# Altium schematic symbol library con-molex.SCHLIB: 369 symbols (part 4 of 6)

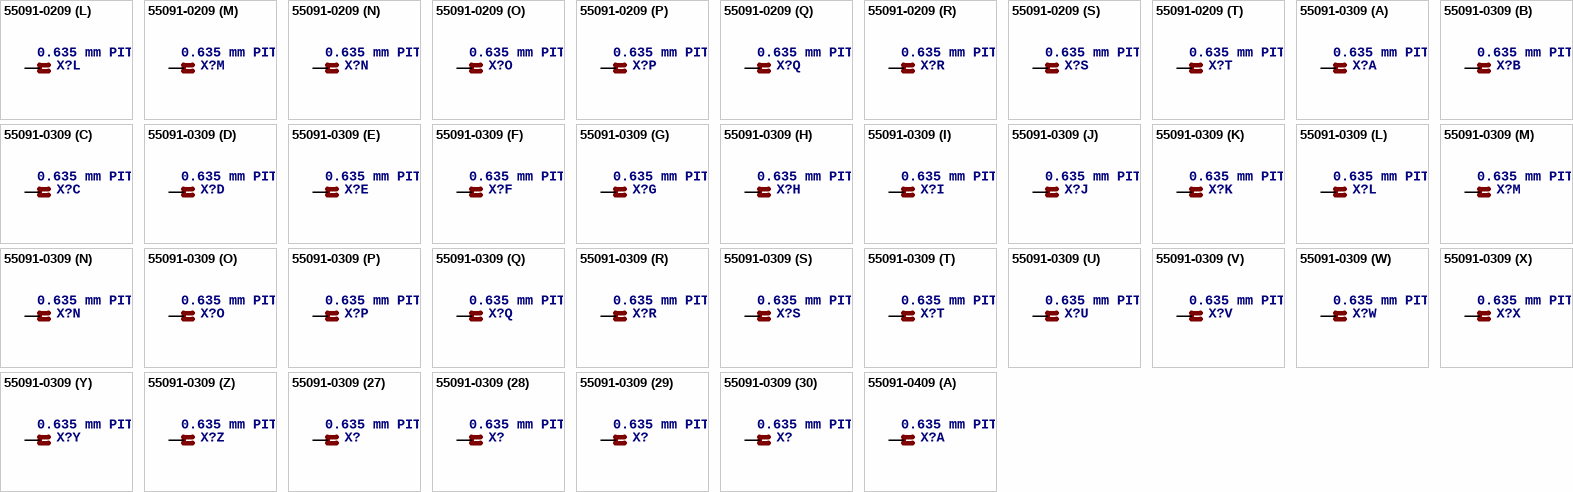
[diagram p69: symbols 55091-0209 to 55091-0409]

## 55091-0209
designator X?, comment 0.635 mm PITCH B TO B CONN.   Source: http://www.molex.com/pdm_docs/sd/550911609_sd.pdf
footprint 55091-0209
part A pins: 1 S
part B pins: 2 S
part C pins: 3 S
part D pins: 4 S
part E pins: 5 S
part F pins: 6 S
part G pins: 7 S
part H pins: 8 S
part I pins: 9 S
part J pins: 10 S
part K pins: 11 S
part L pins: 12 S
part M pins: 13 S
part N pins: 14 S
part O pins: 15 S
part P pins: 16 S
part Q pins: 17 S
part R pins: 18 S
part S pins: 19 S
part T pins: 20 S

## 55091-0309
designator X?, comment 0.635 mm PITCH B TO B CONN.   Source: http://www.molex.com/pdm_docs/sd/550911609_sd.pdf
footprint 55091-0309
part A pins: 1 S
part B pins: 2 S
part C pins: 3 S
part D pins: 4 S
part E pins: 5 S
part F pins: 6 S
part G pins: 7 S
part H pins: 8 S
part I pins: 9 S
part J pins: 10 S
part K pins: 11 S
part L pins: 12 S
part M pins: 13 S
part N pins: 14 S
part O pins: 15 S
part P pins: 16 S
part Q pins: 17 S
part R pins: 18 S
part S pins: 19 S
part T pins: 20 S
part U pins: 21 S
part V pins: 22 S
part W pins: 23 S
part X pins: 24 S
part Y pins: 25 S
part Z pins: 26 S
part 27 pins: 27 S
part 28 pins: 28 S
part 29 pins: 29 S
part 30 pins: 30 S

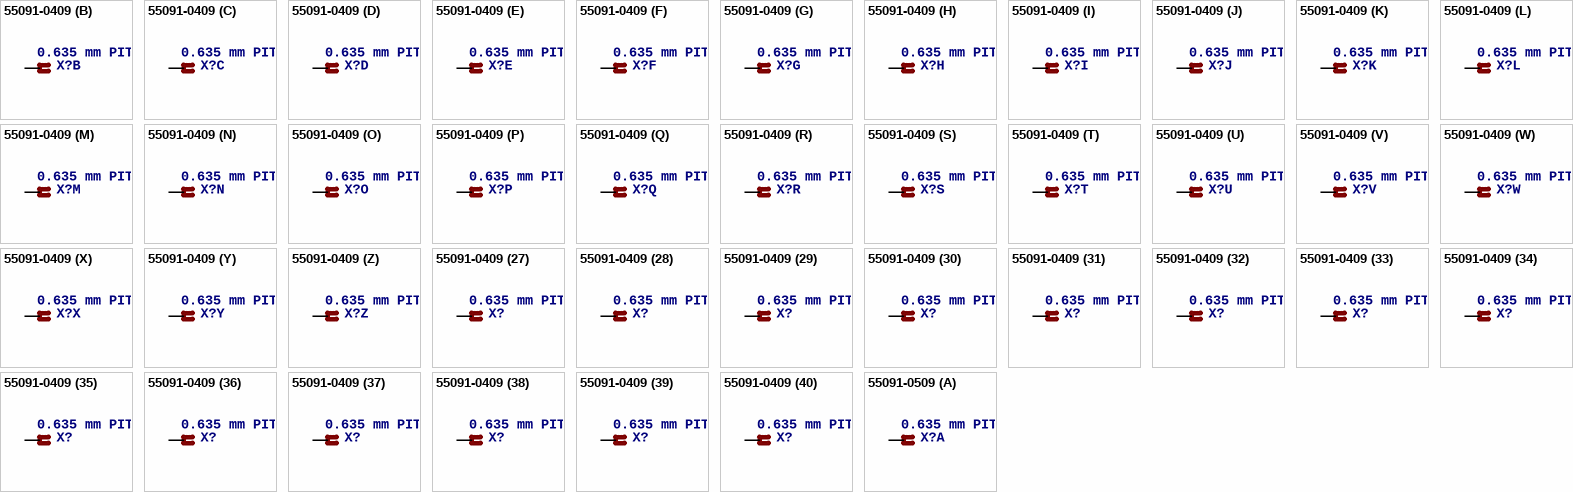
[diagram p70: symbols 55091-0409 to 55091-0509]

## 55091-0409
designator X?, comment 0.635 mm PITCH B TO B CONN.   Source: http://www.molex.com/pdm_docs/sd/550911609_sd.pdf
footprint 55091-0409
part A pins: 1 S
part B pins: 2 S
part C pins: 3 S
part D pins: 4 S
part E pins: 5 S
part F pins: 6 S
part G pins: 7 S
part H pins: 8 S
part I pins: 9 S
part J pins: 10 S
part K pins: 11 S
part L pins: 12 S
part M pins: 13 S
part N pins: 14 S
part O pins: 15 S
part P pins: 16 S
part Q pins: 17 S
part R pins: 18 S
part S pins: 19 S
part T pins: 20 S
part U pins: 21 S
part V pins: 22 S
part W pins: 23 S
part X pins: 24 S
part Y pins: 25 S
part Z pins: 26 S
part 27 pins: 27 S
part 28 pins: 28 S
part 29 pins: 29 S
part 30 pins: 30 S
part 31 pins: 31 S
part 32 pins: 32 S
part 33 pins: 33 S
part 34 pins: 34 S
part 35 pins: 35 S
part 36 pins: 36 S
part 37 pins: 37 S
part 38 pins: 38 S
part 39 pins: 39 S
part 40 pins: 40 S

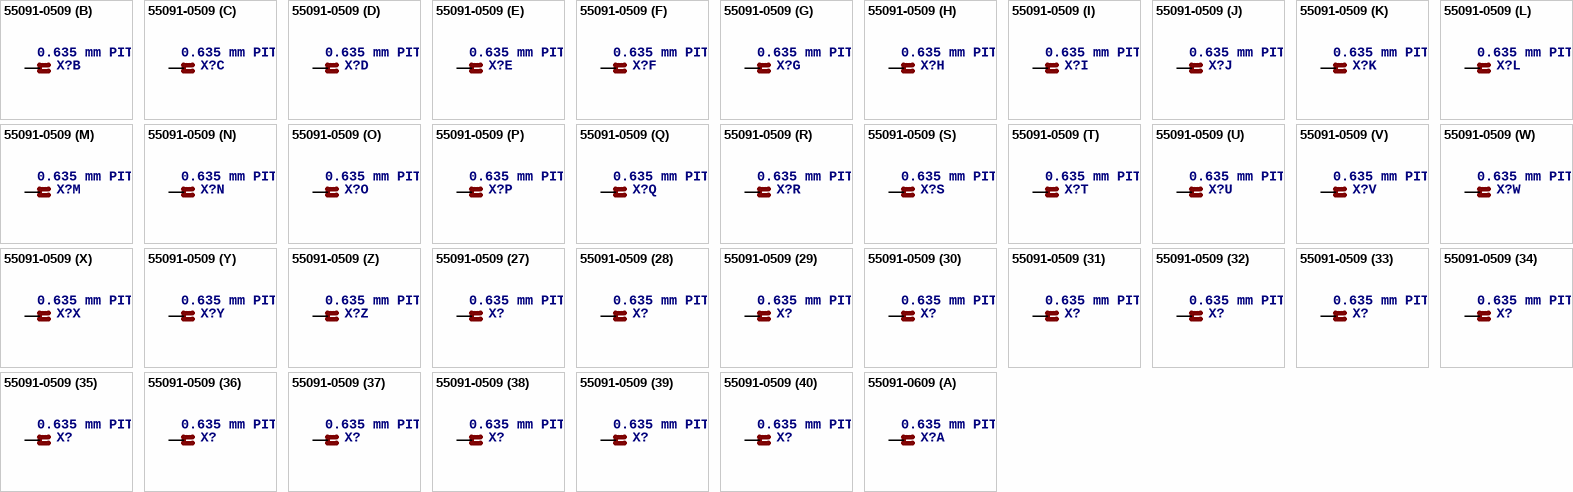
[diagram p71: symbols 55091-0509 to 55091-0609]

## 55091-0509
designator X?, comment 0.635 mm PITCH B TO B CONN.   Source: http://www.molex.com/pdm_docs/sd/550911609_sd.pdf
footprint 55091-0509
part A pins: 1 S
part B pins: 2 S
part C pins: 3 S
part D pins: 4 S
part E pins: 5 S
part F pins: 6 S
part G pins: 7 S
part H pins: 8 S
part I pins: 9 S
part J pins: 10 S
part K pins: 11 S
part L pins: 12 S
part M pins: 13 S
part N pins: 14 S
part O pins: 15 S
part P pins: 16 S
part Q pins: 17 S
part R pins: 18 S
part S pins: 19 S
part T pins: 20 S
part U pins: 21 S
part V pins: 22 S
part W pins: 23 S
part X pins: 24 S
part Y pins: 25 S
part Z pins: 26 S
part 27 pins: 27 S
part 28 pins: 28 S
part 29 pins: 29 S
part 30 pins: 30 S
part 31 pins: 31 S
part 32 pins: 32 S
part 33 pins: 33 S
part 34 pins: 34 S
part 35 pins: 35 S
part 36 pins: 36 S
part 37 pins: 37 S
part 38 pins: 38 S
part 39 pins: 39 S
part 40 pins: 40 S
part 41 pins: 41 S
part 42 pins: 42 S
part 43 pins: 43 S
part 44 pins: 44 S
part 45 pins: 45 S
part 46 pins: 46 S
part 47 pins: 47 S
part 48 pins: 48 S
part 49 pins: 49 S
part 50 pins: 50 S

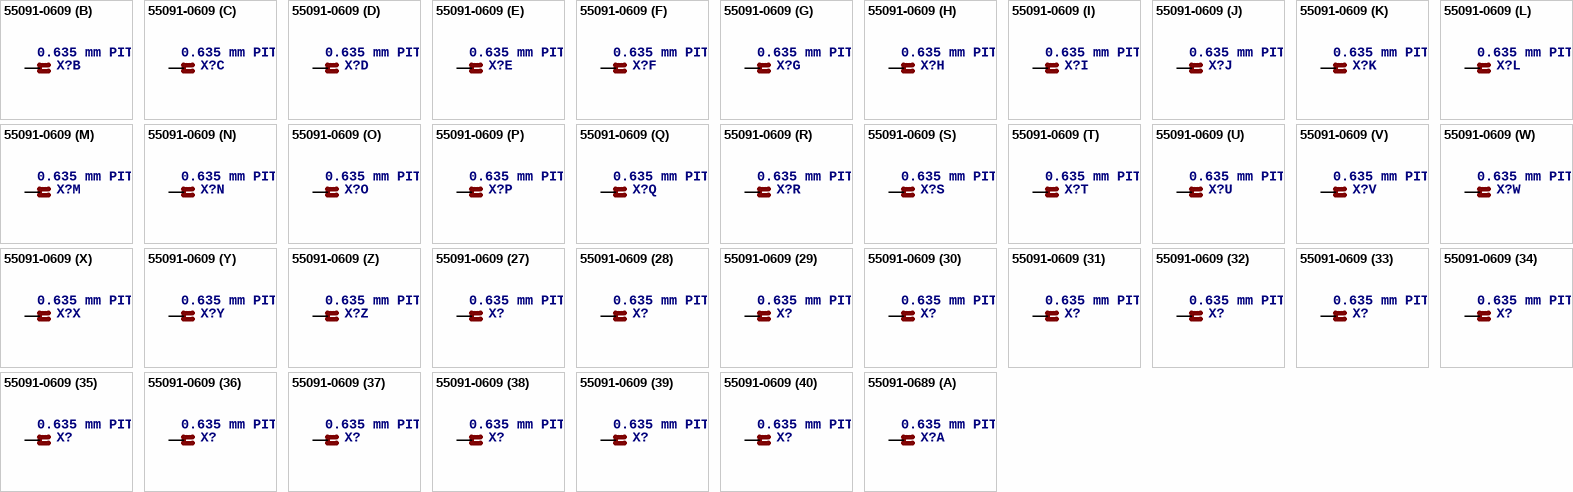
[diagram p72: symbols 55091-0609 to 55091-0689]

## 55091-0609
designator X?, comment 0.635 mm PITCH B TO B CONN.   Source: http://www.molex.com/pdm_docs/sd/550911609_sd.pdf
footprint 55091-0609
part A pins: 1 S
part B pins: 2 S
part C pins: 3 S
part D pins: 4 S
part E pins: 5 S
part F pins: 6 S
part G pins: 7 S
part H pins: 8 S
part I pins: 9 S
part J pins: 10 S
part K pins: 11 S
part L pins: 12 S
part M pins: 13 S
part N pins: 14 S
part O pins: 15 S
part P pins: 16 S
part Q pins: 17 S
part R pins: 18 S
part S pins: 19 S
part T pins: 20 S
part U pins: 21 S
part V pins: 22 S
part W pins: 23 S
part X pins: 24 S
part Y pins: 25 S
part Z pins: 26 S
part 27 pins: 27 S
part 28 pins: 28 S
part 29 pins: 29 S
part 30 pins: 30 S
part 31 pins: 31 S
part 32 pins: 32 S
part 33 pins: 33 S
part 34 pins: 34 S
part 35 pins: 35 S
part 36 pins: 36 S
part 37 pins: 37 S
part 38 pins: 38 S
part 39 pins: 39 S
part 40 pins: 40 S
part 41 pins: 41 S
part 42 pins: 42 S
part 43 pins: 43 S
part 44 pins: 44 S
part 45 pins: 45 S
part 46 pins: 46 S
part 47 pins: 47 S
part 48 pins: 48 S
part 49 pins: 49 S
part 50 pins: 50 S
part 51 pins: 51 S
part 52 pins: 52 S
part 53 pins: 53 S
part 54 pins: 54 S
part 55 pins: 55 S
part 56 pins: 56 S
part 57 pins: 57 S
part 58 pins: 58 S
part 59 pins: 59 S
part 60 pins: 60 S

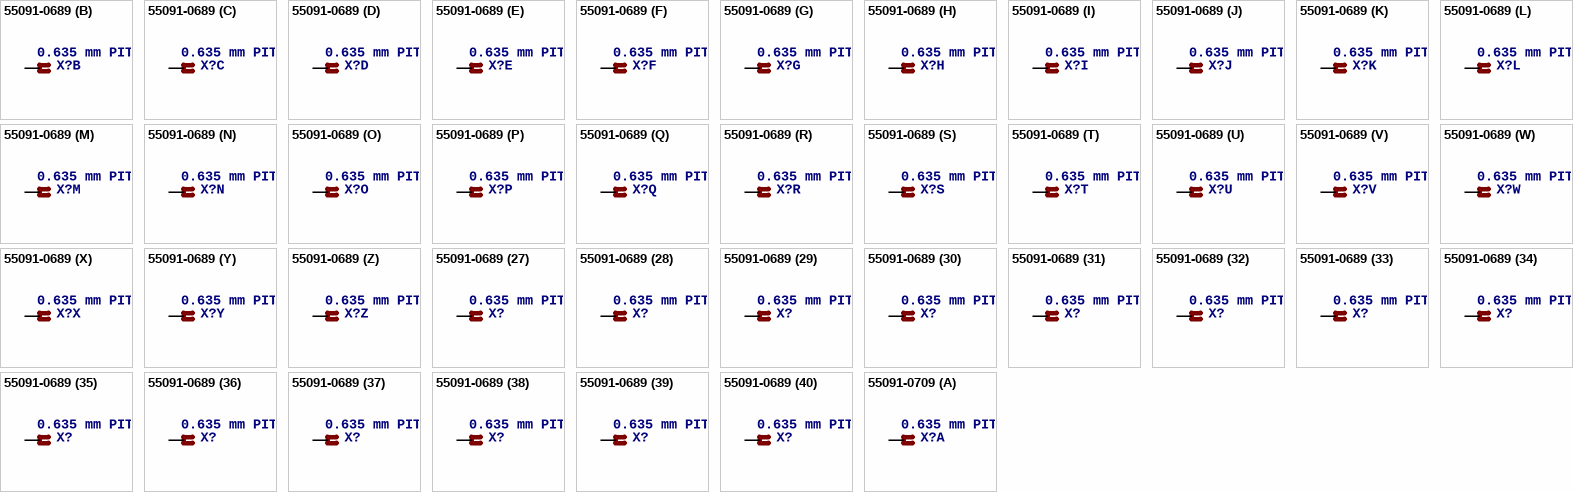
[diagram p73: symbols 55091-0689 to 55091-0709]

## 55091-0689
designator X?, comment 0.635 mm PITCH B TO B CONN.   Source: http://www.molex.com/pdm_docs/sd/550911609_sd.pdf
footprint 55091-0689
part A pins: 1 S
part B pins: 2 S
part C pins: 3 S
part D pins: 4 S
part E pins: 5 S
part F pins: 6 S
part G pins: 7 S
part H pins: 8 S
part I pins: 9 S
part J pins: 10 S
part K pins: 11 S
part L pins: 12 S
part M pins: 13 S
part N pins: 14 S
part O pins: 15 S
part P pins: 16 S
part Q pins: 17 S
part R pins: 18 S
part S pins: 19 S
part T pins: 20 S
part U pins: 21 S
part V pins: 22 S
part W pins: 23 S
part X pins: 24 S
part Y pins: 25 S
part Z pins: 26 S
part 27 pins: 27 S
part 28 pins: 28 S
part 29 pins: 29 S
part 30 pins: 30 S
part 31 pins: 31 S
part 32 pins: 32 S
part 33 pins: 33 S
part 34 pins: 34 S
part 35 pins: 35 S
part 36 pins: 36 S
part 37 pins: 37 S
part 38 pins: 38 S
part 39 pins: 39 S
part 40 pins: 40 S
part 41 pins: 41 S
part 42 pins: 42 S
part 43 pins: 43 S
part 44 pins: 44 S
part 45 pins: 45 S
part 46 pins: 46 S
part 47 pins: 47 S
part 48 pins: 48 S
part 49 pins: 49 S
part 50 pins: 50 S
part 51 pins: 51 S
part 52 pins: 52 S
part 53 pins: 53 S
part 54 pins: 54 S
part 55 pins: 55 S
part 56 pins: 56 S
part 57 pins: 57 S
part 58 pins: 58 S
part 59 pins: 59 S
part 60 pins: 60 S
part 61 pins: 61 S
part 62 pins: 62 S
part 63 pins: 63 S
part 64 pins: 64 S
part 65 pins: 65 S
part 66 pins: 66 S
part 67 pins: 67 S
part 68 pins: 68 S

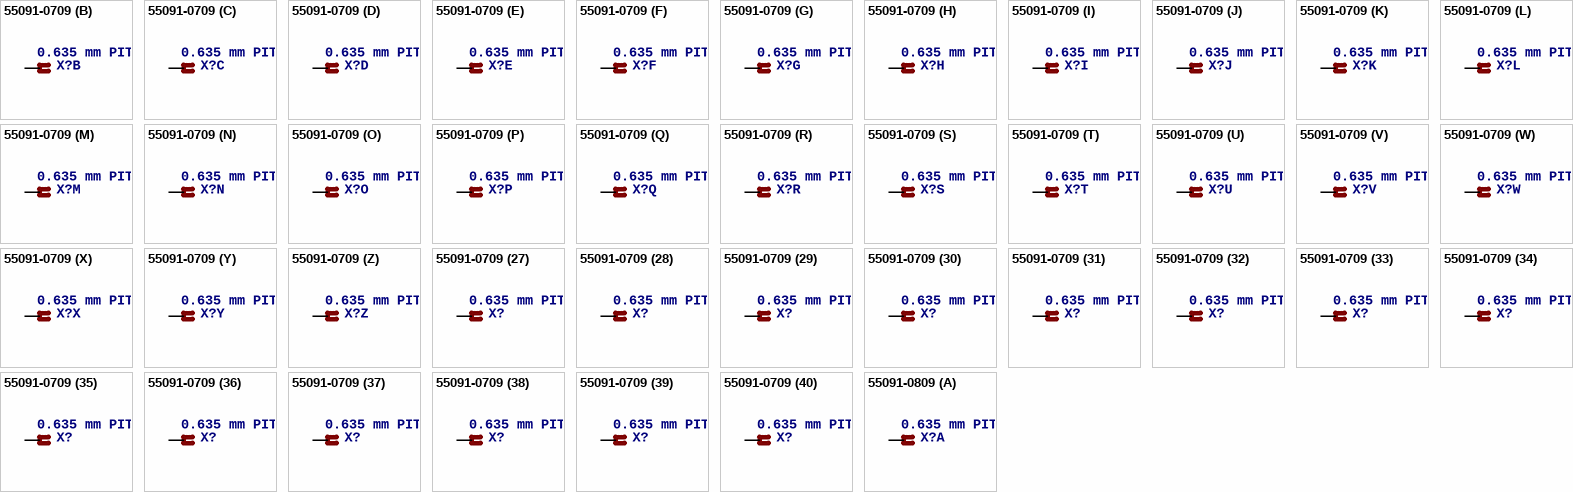
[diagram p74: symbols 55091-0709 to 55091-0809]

## 55091-0709
designator X?, comment 0.635 mm PITCH B TO B CONN.   Source: http://www.molex.com/pdm_docs/sd/550911609_sd.pdf
footprint 55091-0709
part A pins: 1 S
part B pins: 2 S
part C pins: 3 S
part D pins: 4 S
part E pins: 5 S
part F pins: 6 S
part G pins: 7 S
part H pins: 8 S
part I pins: 9 S
part J pins: 10 S
part K pins: 11 S
part L pins: 12 S
part M pins: 13 S
part N pins: 14 S
part O pins: 15 S
part P pins: 16 S
part Q pins: 17 S
part R pins: 18 S
part S pins: 19 S
part T pins: 20 S
part U pins: 21 S
part V pins: 22 S
part W pins: 23 S
part X pins: 24 S
part Y pins: 25 S
part Z pins: 26 S
part 27 pins: 27 S
part 28 pins: 28 S
part 29 pins: 29 S
part 30 pins: 30 S
part 31 pins: 31 S
part 32 pins: 32 S
part 33 pins: 33 S
part 34 pins: 34 S
part 35 pins: 35 S
part 36 pins: 36 S
part 37 pins: 37 S
part 38 pins: 38 S
part 39 pins: 39 S
part 40 pins: 40 S
part 41 pins: 41 S
part 42 pins: 42 S
part 43 pins: 43 S
part 44 pins: 44 S
part 45 pins: 45 S
part 46 pins: 46 S
part 47 pins: 47 S
part 48 pins: 48 S
part 49 pins: 49 S
part 50 pins: 50 S
part 51 pins: 51 S
part 52 pins: 52 S
part 53 pins: 53 S
part 54 pins: 54 S
part 55 pins: 55 S
part 56 pins: 56 S
part 57 pins: 57 S
part 58 pins: 58 S
part 59 pins: 59 S
part 60 pins: 60 S
part 61 pins: 61 S
part 62 pins: 62 S
part 63 pins: 63 S
part 64 pins: 64 S
part 65 pins: 65 S
part 66 pins: 66 S
part 67 pins: 67 S
part 68 pins: 68 S
part 69 pins: 69 S
part 70 pins: 70 S

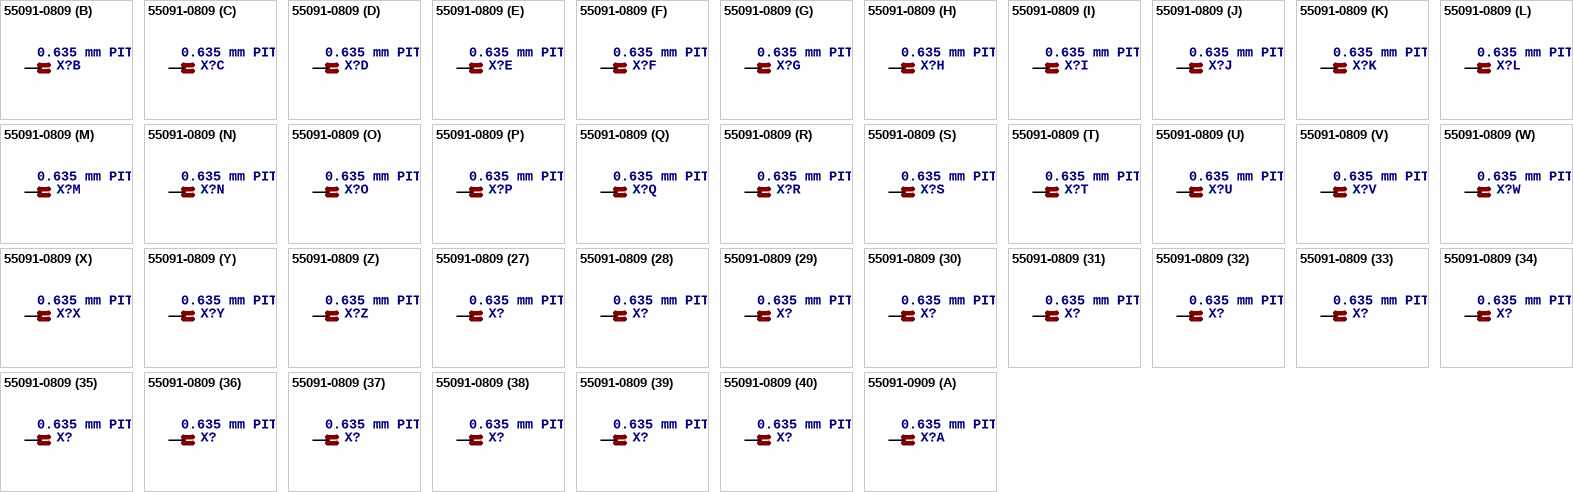
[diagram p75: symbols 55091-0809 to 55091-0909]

## 55091-0809
designator X?, comment 0.635 mm PITCH B TO B CONN.   Source: http://www.molex.com/pdm_docs/sd/550911609_sd.pdf
footprint 55091-0809
part A pins: 1 S
part B pins: 2 S
part C pins: 3 S
part D pins: 4 S
part E pins: 5 S
part F pins: 6 S
part G pins: 7 S
part H pins: 8 S
part I pins: 9 S
part J pins: 10 S
part K pins: 11 S
part L pins: 12 S
part M pins: 13 S
part N pins: 14 S
part O pins: 15 S
part P pins: 16 S
part Q pins: 17 S
part R pins: 18 S
part S pins: 19 S
part T pins: 20 S
part U pins: 21 S
part V pins: 22 S
part W pins: 23 S
part X pins: 24 S
part Y pins: 25 S
part Z pins: 26 S
part 27 pins: 27 S
part 28 pins: 28 S
part 29 pins: 29 S
part 30 pins: 30 S
part 31 pins: 31 S
part 32 pins: 32 S
part 33 pins: 33 S
part 34 pins: 34 S
part 35 pins: 35 S
part 36 pins: 36 S
part 37 pins: 37 S
part 38 pins: 38 S
part 39 pins: 39 S
part 40 pins: 40 S
part 41 pins: 41 S
part 42 pins: 42 S
part 43 pins: 43 S
part 44 pins: 44 S
part 45 pins: 45 S
part 46 pins: 46 S
part 47 pins: 47 S
part 48 pins: 48 S
part 49 pins: 49 S
part 50 pins: 50 S
part 51 pins: 51 S
part 52 pins: 52 S
part 53 pins: 53 S
part 54 pins: 54 S
part 55 pins: 55 S
part 56 pins: 56 S
part 57 pins: 57 S
part 58 pins: 58 S
part 59 pins: 59 S
part 60 pins: 60 S
part 61 pins: 61 S
part 62 pins: 62 S
part 63 pins: 63 S
part 64 pins: 64 S
part 65 pins: 65 S
part 66 pins: 66 S
part 67 pins: 67 S
part 68 pins: 68 S
part 69 pins: 69 S
part 70 pins: 70 S
part 71 pins: 71 S
part 72 pins: 72 S
part 73 pins: 73 S
part 74 pins: 74 S
part 75 pins: 75 S
part 76 pins: 76 S
part 77 pins: 77 S
part 78 pins: 78 S
part 79 pins: 79 S
part 80 pins: 80 S

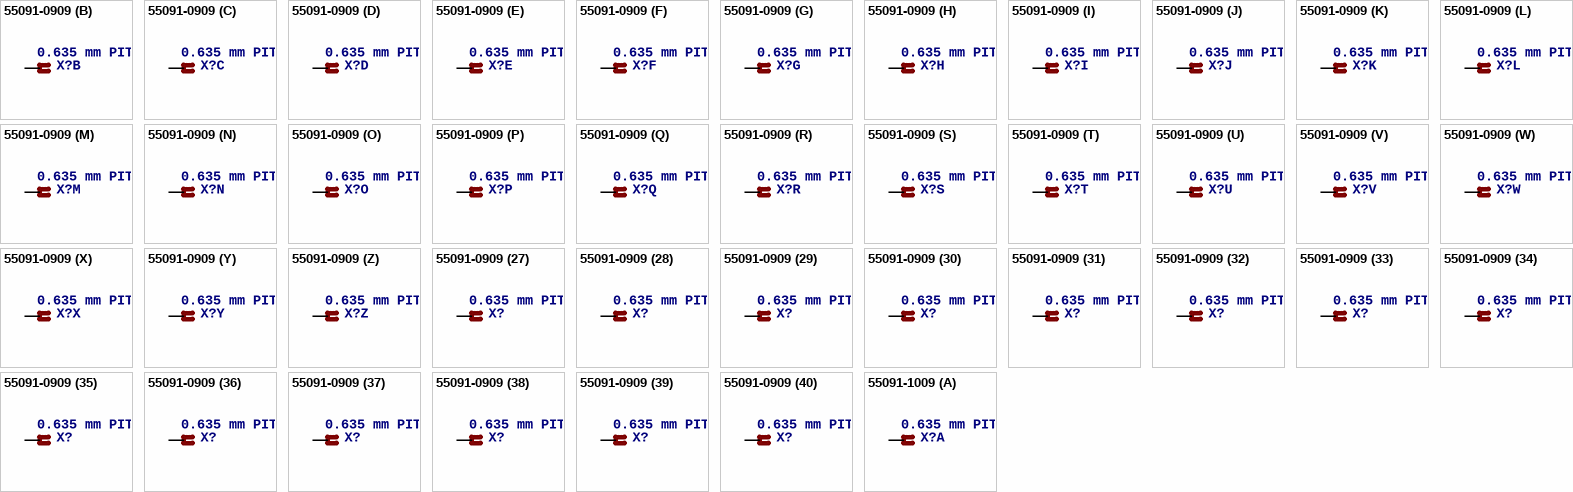
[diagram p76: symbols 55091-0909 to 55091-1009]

## 55091-0909
designator X?, comment 0.635 mm PITCH B TO B CONN.   Source: http://www.molex.com/pdm_docs/sd/550911609_sd.pdf
footprint 55091-0909
part A pins: 1 S
part B pins: 2 S
part C pins: 3 S
part D pins: 4 S
part E pins: 5 S
part F pins: 6 S
part G pins: 7 S
part H pins: 8 S
part I pins: 9 S
part J pins: 10 S
part K pins: 11 S
part L pins: 12 S
part M pins: 13 S
part N pins: 14 S
part O pins: 15 S
part P pins: 16 S
part Q pins: 17 S
part R pins: 18 S
part S pins: 19 S
part T pins: 20 S
part U pins: 21 S
part V pins: 22 S
part W pins: 23 S
part X pins: 24 S
part Y pins: 25 S
part Z pins: 26 S
part 27 pins: 27 S
part 28 pins: 28 S
part 29 pins: 29 S
part 30 pins: 30 S
part 31 pins: 31 S
part 32 pins: 32 S
part 33 pins: 33 S
part 34 pins: 34 S
part 35 pins: 35 S
part 36 pins: 36 S
part 37 pins: 37 S
part 38 pins: 38 S
part 39 pins: 39 S
part 40 pins: 40 S
part 41 pins: 41 S
part 42 pins: 42 S
part 43 pins: 43 S
part 44 pins: 44 S
part 45 pins: 45 S
part 46 pins: 46 S
part 47 pins: 47 S
part 48 pins: 48 S
part 49 pins: 49 S
part 50 pins: 50 S
part 51 pins: 51 S
part 52 pins: 52 S
part 53 pins: 53 S
part 54 pins: 54 S
part 55 pins: 55 S
part 56 pins: 56 S
part 57 pins: 57 S
part 58 pins: 58 S
part 59 pins: 59 S
part 60 pins: 60 S
part 61 pins: 61 S
part 62 pins: 62 S
part 63 pins: 63 S
part 64 pins: 64 S
part 65 pins: 65 S
part 66 pins: 66 S
part 67 pins: 67 S
part 68 pins: 68 S
part 69 pins: 69 S
part 70 pins: 70 S
part 71 pins: 71 S
part 72 pins: 72 S
part 73 pins: 73 S
part 74 pins: 74 S
part 75 pins: 75 S
part 76 pins: 76 S
part 77 pins: 77 S
part 78 pins: 78 S
part 79 pins: 79 S
part 80 pins: 80 S
part 81 pins: 81 S
part 82 pins: 82 S
part 83 pins: 83 S
part 84 pins: 84 S
part 85 pins: 85 S
part 86 pins: 86 S
part 87 pins: 87 S
part 88 pins: 88 S
part 89 pins: 89 S
part 90 pins: 90 S

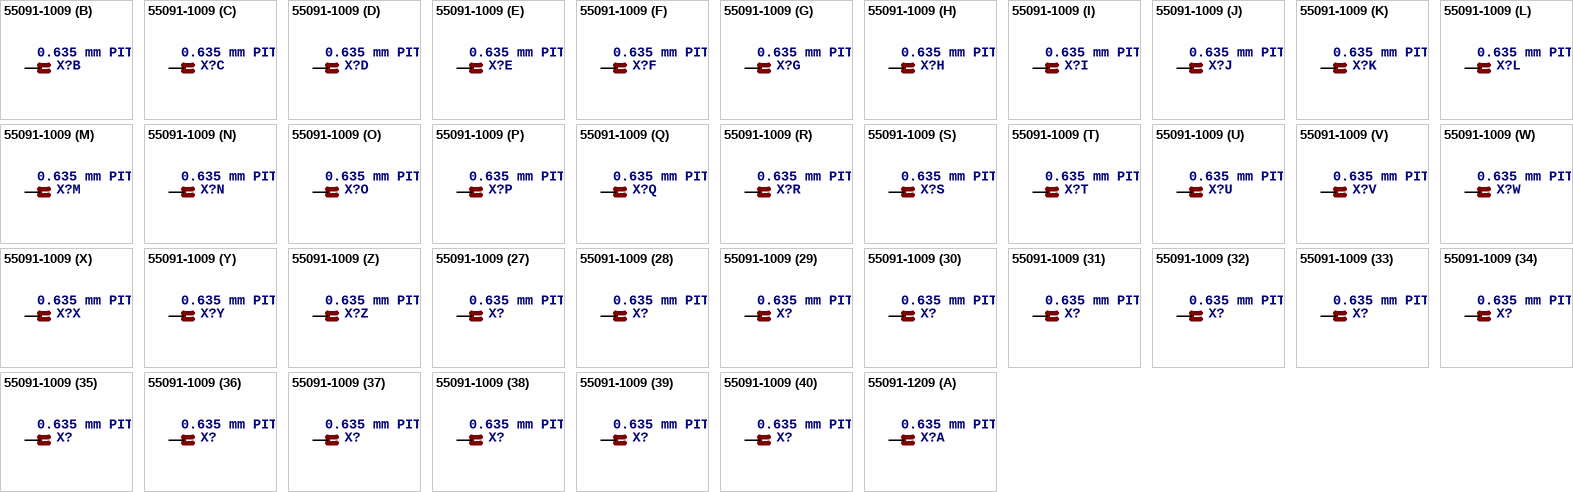
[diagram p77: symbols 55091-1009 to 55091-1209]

## 55091-1009
designator X?, comment 0.635 mm PITCH B TO B CONN.   Source: http://www.molex.com/pdm_docs/sd/550911609_sd.pdf
footprint 55091-1009
part A pins: 1 S
part B pins: 2 S
part C pins: 3 S
part D pins: 4 S
part E pins: 5 S
part F pins: 6 S
part G pins: 7 S
part H pins: 8 S
part I pins: 9 S
part J pins: 10 S
part K pins: 11 S
part L pins: 12 S
part M pins: 13 S
part N pins: 14 S
part O pins: 15 S
part P pins: 16 S
part Q pins: 17 S
part R pins: 18 S
part S pins: 19 S
part T pins: 20 S
part U pins: 21 S
part V pins: 22 S
part W pins: 23 S
part X pins: 24 S
part Y pins: 25 S
part Z pins: 26 S
part 27 pins: 27 S
part 28 pins: 28 S
part 29 pins: 29 S
part 30 pins: 30 S
part 31 pins: 31 S
part 32 pins: 32 S
part 33 pins: 33 S
part 34 pins: 34 S
part 35 pins: 35 S
part 36 pins: 36 S
part 37 pins: 37 S
part 38 pins: 38 S
part 39 pins: 39 S
part 40 pins: 40 S
part 41 pins: 41 S
part 42 pins: 42 S
part 43 pins: 43 S
part 44 pins: 44 S
part 45 pins: 45 S
part 46 pins: 46 S
part 47 pins: 47 S
part 48 pins: 48 S
part 49 pins: 49 S
part 50 pins: 50 S
part 51 pins: 51 S
part 52 pins: 52 S
part 53 pins: 53 S
part 54 pins: 54 S
part 55 pins: 55 S
part 56 pins: 56 S
part 57 pins: 57 S
part 58 pins: 58 S
part 59 pins: 59 S
part 60 pins: 60 S
part 61 pins: 61 S
part 62 pins: 62 S
part 63 pins: 63 S
part 64 pins: 64 S
part 65 pins: 65 S
part 66 pins: 66 S
part 67 pins: 67 S
part 68 pins: 68 S
part 69 pins: 69 S
part 70 pins: 70 S
part 71 pins: 71 S
part 72 pins: 72 S
part 73 pins: 73 S
part 74 pins: 74 S
part 75 pins: 75 S
part 76 pins: 76 S
part 77 pins: 77 S
part 78 pins: 78 S
part 79 pins: 79 S
part 80 pins: 80 S
part 81 pins: 81 S
part 82 pins: 82 S
part 83 pins: 83 S
part 84 pins: 84 S
part 85 pins: 85 S
part 86 pins: 86 S
part 87 pins: 87 S
part 88 pins: 88 S
part 89 pins: 89 S
part 90 pins: 90 S
part 91 pins: 91 S
part 92 pins: 92 S
part 93 pins: 93 S
part 94 pins: 94 S
part 95 pins: 95 S
part 96 pins: 96 S
part 97 pins: 97 S
part 98 pins: 98 S
part 99 pins: 99 S
part 100 pins: 100 S

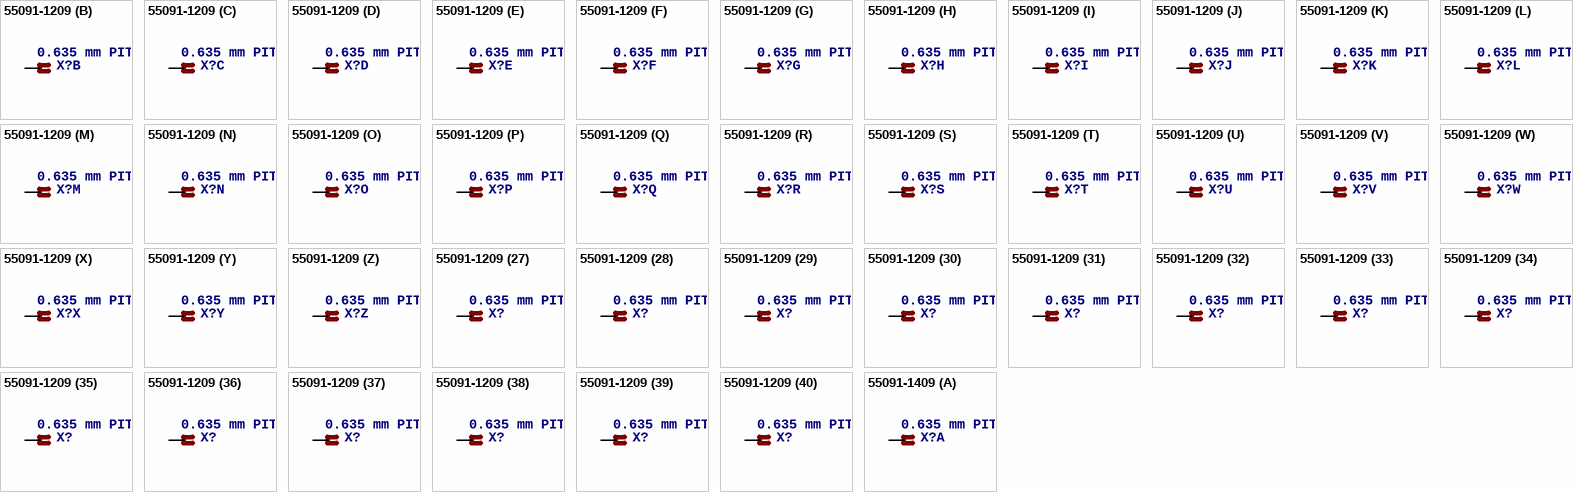
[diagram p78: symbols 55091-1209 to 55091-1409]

## 55091-1209
designator X?, comment 0.635 mm PITCH B TO B CONN.   Source: http://www.molex.com/pdm_docs/sd/550911609_sd.pdf
footprint 55091-1209
part A pins: 1 S
part B pins: 2 S
part C pins: 3 S
part D pins: 4 S
part E pins: 5 S
part F pins: 6 S
part G pins: 7 S
part H pins: 8 S
part I pins: 9 S
part J pins: 10 S
part K pins: 11 S
part L pins: 12 S
part M pins: 13 S
part N pins: 14 S
part O pins: 15 S
part P pins: 16 S
part Q pins: 17 S
part R pins: 18 S
part S pins: 19 S
part T pins: 20 S
part U pins: 21 S
part V pins: 22 S
part W pins: 23 S
part X pins: 24 S
part Y pins: 25 S
part Z pins: 26 S
part 27 pins: 27 S
part 28 pins: 28 S
part 29 pins: 29 S
part 30 pins: 30 S
part 31 pins: 31 S
part 32 pins: 32 S
part 33 pins: 33 S
part 34 pins: 34 S
part 35 pins: 35 S
part 36 pins: 36 S
part 37 pins: 37 S
part 38 pins: 38 S
part 39 pins: 39 S
part 40 pins: 40 S
part 41 pins: 41 S
part 42 pins: 42 S
part 43 pins: 43 S
part 44 pins: 44 S
part 45 pins: 45 S
part 46 pins: 46 S
part 47 pins: 47 S
part 48 pins: 48 S
part 49 pins: 49 S
part 50 pins: 50 S
part 51 pins: 51 S
part 52 pins: 52 S
part 53 pins: 53 S
part 54 pins: 54 S
part 55 pins: 55 S
part 56 pins: 56 S
part 57 pins: 57 S
part 58 pins: 58 S
part 59 pins: 59 S
part 60 pins: 60 S
part 61 pins: 61 S
part 62 pins: 62 S
part 63 pins: 63 S
part 64 pins: 64 S
part 65 pins: 65 S
part 66 pins: 66 S
part 67 pins: 67 S
part 68 pins: 68 S
part 69 pins: 69 S
part 70 pins: 70 S
part 71 pins: 71 S
part 72 pins: 72 S
part 73 pins: 73 S
part 74 pins: 74 S
part 75 pins: 75 S
part 76 pins: 76 S
part 77 pins: 77 S
part 78 pins: 78 S
part 79 pins: 79 S
part 80 pins: 80 S
part 81 pins: 81 S
part 82 pins: 82 S
part 83 pins: 83 S
part 84 pins: 84 S
part 85 pins: 85 S
part 86 pins: 86 S
part 87 pins: 87 S
part 88 pins: 88 S
part 89 pins: 89 S
part 90 pins: 90 S
part 91 pins: 91 S
part 92 pins: 92 S
part 93 pins: 93 S
part 94 pins: 94 S
part 95 pins: 95 S
part 96 pins: 96 S
part 97 pins: 97 S
part 98 pins: 98 S
part 99 pins: 99 S
part 100 pins: 100 S
part 101 pins: 101 S
part 102 pins: 102 S
part 103 pins: 103 S
part 104 pins: 104 S
part 105 pins: 105 S
part 106 pins: 106 S
part 107 pins: 107 S
part 108 pins: 108 S
part 109 pins: 109 S
part 110 pins: 110 S
part 111 pins: 111 S
part 112 pins: 112 S
part 113 pins: 113 S
part 114 pins: 114 S
part 115 pins: 115 S
part 116 pins: 116 S
part 117 pins: 117 S
part 118 pins: 118 S
part 119 pins: 119 S
part 120 pins: 120 S

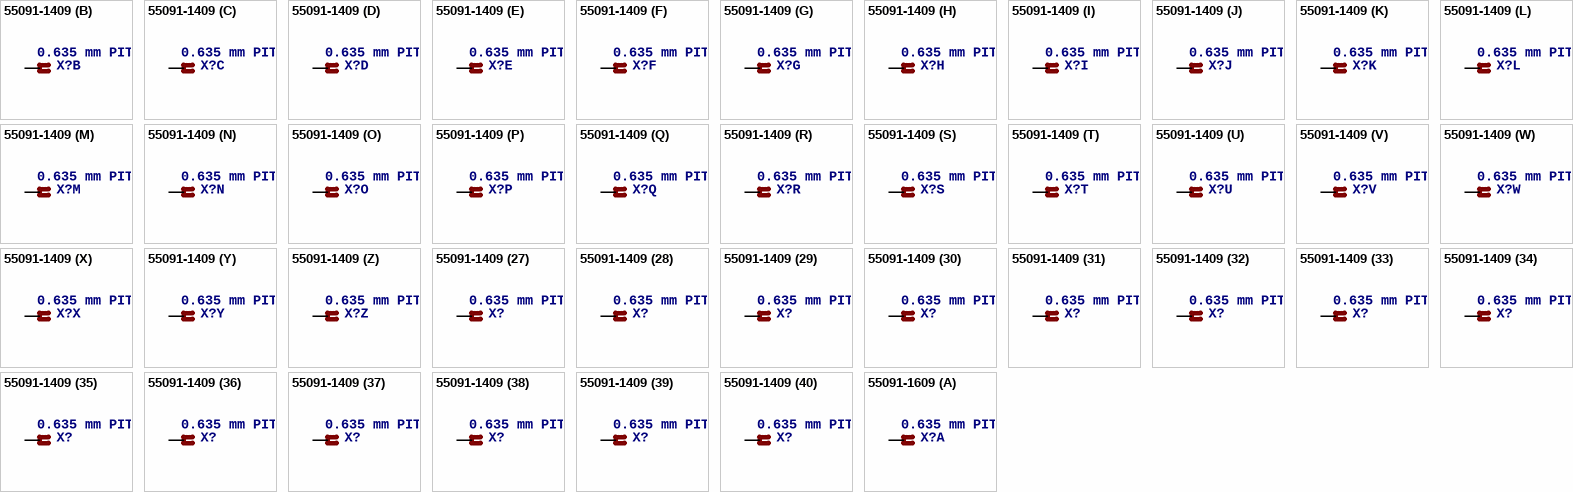
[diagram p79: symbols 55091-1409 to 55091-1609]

## 55091-1409
designator X?, comment 0.635 mm PITCH B TO B CONN.   Source: http://www.molex.com/pdm_docs/sd/550911609_sd.pdf
footprint 55091-1409
part A pins: 1 S
part B pins: 2 S
part C pins: 3 S
part D pins: 4 S
part E pins: 5 S
part F pins: 6 S
part G pins: 7 S
part H pins: 8 S
part I pins: 9 S
part J pins: 10 S
part K pins: 11 S
part L pins: 12 S
part M pins: 13 S
part N pins: 14 S
part O pins: 15 S
part P pins: 16 S
part Q pins: 17 S
part R pins: 18 S
part S pins: 19 S
part T pins: 20 S
part U pins: 21 S
part V pins: 22 S
part W pins: 23 S
part X pins: 24 S
part Y pins: 25 S
part Z pins: 26 S
part 27 pins: 27 S
part 28 pins: 28 S
part 29 pins: 29 S
part 30 pins: 30 S
part 31 pins: 31 S
part 32 pins: 32 S
part 33 pins: 33 S
part 34 pins: 34 S
part 35 pins: 35 S
part 36 pins: 36 S
part 37 pins: 37 S
part 38 pins: 38 S
part 39 pins: 39 S
part 40 pins: 40 S
part 41 pins: 41 S
part 42 pins: 42 S
part 43 pins: 43 S
part 44 pins: 44 S
part 45 pins: 45 S
part 46 pins: 46 S
part 47 pins: 47 S
part 48 pins: 48 S
part 49 pins: 49 S
part 50 pins: 50 S
part 51 pins: 51 S
part 52 pins: 52 S
part 53 pins: 53 S
part 54 pins: 54 S
part 55 pins: 55 S
part 56 pins: 56 S
part 57 pins: 57 S
part 58 pins: 58 S
part 59 pins: 59 S
part 60 pins: 60 S
part 61 pins: 61 S
part 62 pins: 62 S
part 63 pins: 63 S
part 64 pins: 64 S
part 65 pins: 65 S
part 66 pins: 66 S
part 67 pins: 67 S
part 68 pins: 68 S
part 69 pins: 69 S
part 70 pins: 70 S
part 71 pins: 71 S
part 72 pins: 72 S
part 73 pins: 73 S
part 74 pins: 74 S
part 75 pins: 75 S
part 76 pins: 76 S
part 77 pins: 77 S
part 78 pins: 78 S
part 79 pins: 79 S
part 80 pins: 80 S
part 81 pins: 81 S
part 82 pins: 82 S
part 83 pins: 83 S
part 84 pins: 84 S
part 85 pins: 85 S
part 86 pins: 86 S
part 87 pins: 87 S
part 88 pins: 88 S
part 89 pins: 89 S
part 90 pins: 90 S
part 91 pins: 91 S
part 92 pins: 92 S
part 93 pins: 93 S
part 94 pins: 94 S
part 95 pins: 95 S
part 96 pins: 96 S
part 97 pins: 97 S
part 98 pins: 98 S
part 99 pins: 99 S
part 100 pins: 100 S
part 101 pins: 101 S
part 102 pins: 102 S
part 103 pins: 103 S
part 104 pins: 104 S
part 105 pins: 105 S
part 106 pins: 106 S
part 107 pins: 107 S
part 108 pins: 108 S
part 109 pins: 109 S
part 110 pins: 110 S
part 111 pins: 111 S
part 112 pins: 112 S
part 113 pins: 113 S
part 114 pins: 114 S
part 115 pins: 115 S
part 116 pins: 116 S
part 117 pins: 117 S
part 118 pins: 118 S
part 119 pins: 119 S
part 120 pins: 120 S
part 121 pins: 121 S
part 122 pins: 122 S
part 123 pins: 123 S
part 124 pins: 124 S
part 125 pins: 125 S
part 126 pins: 126 S
part 127 pins: 127 S
part 128 pins: 128 S
part 129 pins: 129 S
part 130 pins: 130 S
part 131 pins: 131 S
part 132 pins: 132 S
part 133 pins: 133 S
part 134 pins: 134 S
part 135 pins: 135 S
part 136 pins: 136 S
part 137 pins: 137 S
part 138 pins: 138 S
part 139 pins: 139 S
part 140 pins: 140 S

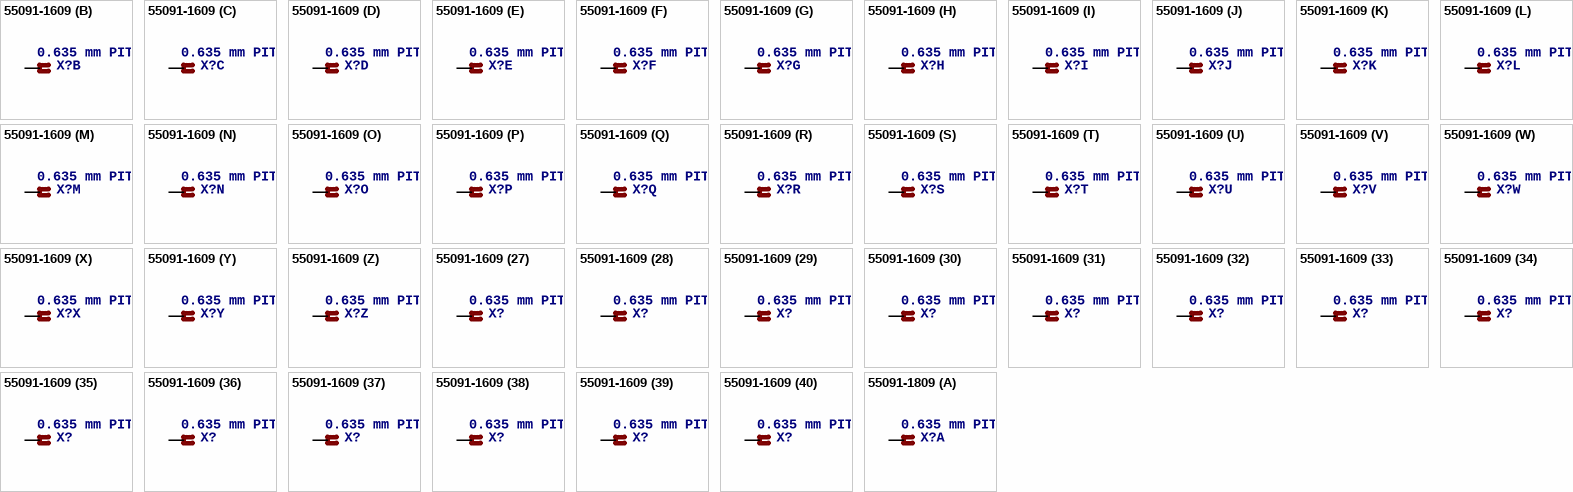
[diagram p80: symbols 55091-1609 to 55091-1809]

## 55091-1609
designator X?, comment 0.635 mm PITCH B TO B CONN.   Source: http://www.molex.com/pdm_docs/sd/550911609_sd.pdf
footprint 55091-1609
part A pins: 1 S
part B pins: 2 S
part C pins: 3 S
part D pins: 4 S
part E pins: 5 S
part F pins: 6 S
part G pins: 7 S
part H pins: 8 S
part I pins: 9 S
part J pins: 10 S
part K pins: 11 S
part L pins: 12 S
part M pins: 13 S
part N pins: 14 S
part O pins: 15 S
part P pins: 16 S
part Q pins: 17 S
part R pins: 18 S
part S pins: 19 S
part T pins: 20 S
part U pins: 21 S
part V pins: 22 S
part W pins: 23 S
part X pins: 24 S
part Y pins: 25 S
part Z pins: 26 S
part 27 pins: 27 S
part 28 pins: 28 S
part 29 pins: 29 S
part 30 pins: 30 S
part 31 pins: 31 S
part 32 pins: 32 S
part 33 pins: 33 S
part 34 pins: 34 S
part 35 pins: 35 S
part 36 pins: 36 S
part 37 pins: 37 S
part 38 pins: 38 S
part 39 pins: 39 S
part 40 pins: 40 S
part 41 pins: 41 S
part 42 pins: 42 S
part 43 pins: 43 S
part 44 pins: 44 S
part 45 pins: 45 S
part 46 pins: 46 S
part 47 pins: 47 S
part 48 pins: 48 S
part 49 pins: 49 S
part 50 pins: 50 S
part 51 pins: 51 S
part 52 pins: 52 S
part 53 pins: 53 S
part 54 pins: 54 S
part 55 pins: 55 S
part 56 pins: 56 S
part 57 pins: 57 S
part 58 pins: 58 S
part 59 pins: 59 S
part 60 pins: 60 S
part 61 pins: 61 S
part 62 pins: 62 S
part 63 pins: 63 S
part 64 pins: 64 S
part 65 pins: 65 S
part 66 pins: 66 S
part 67 pins: 67 S
part 68 pins: 68 S
part 69 pins: 69 S
part 70 pins: 70 S
part 71 pins: 71 S
part 72 pins: 72 S
part 73 pins: 73 S
part 74 pins: 74 S
part 75 pins: 75 S
part 76 pins: 76 S
part 77 pins: 77 S
part 78 pins: 78 S
part 79 pins: 79 S
part 80 pins: 80 S
part 81 pins: 81 S
part 82 pins: 82 S
part 83 pins: 83 S
part 84 pins: 84 S
part 85 pins: 85 S
part 86 pins: 86 S
part 87 pins: 87 S
part 88 pins: 88 S
part 89 pins: 89 S
part 90 pins: 90 S
part 91 pins: 91 S
part 92 pins: 92 S
part 93 pins: 93 S
part 94 pins: 94 S
part 95 pins: 95 S
part 96 pins: 96 S
part 97 pins: 97 S
part 98 pins: 98 S
part 99 pins: 99 S
part 100 pins: 100 S
part 101 pins: 101 S
part 102 pins: 102 S
part 103 pins: 103 S
part 104 pins: 104 S
part 105 pins: 105 S
part 106 pins: 106 S
part 107 pins: 107 S
part 108 pins: 108 S
part 109 pins: 109 S
part 110 pins: 110 S
part 111 pins: 111 S
part 112 pins: 112 S
part 113 pins: 113 S
part 114 pins: 114 S
part 115 pins: 115 S
part 116 pins: 116 S
part 117 pins: 117 S
part 118 pins: 118 S
part 119 pins: 119 S
part 120 pins: 120 S
part 121 pins: 121 S
part 122 pins: 122 S
part 123 pins: 123 S
part 124 pins: 124 S
part 125 pins: 125 S
part 126 pins: 126 S
part 127 pins: 127 S
part 128 pins: 128 S
part 129 pins: 129 S
part 130 pins: 130 S
part 131 pins: 131 S
part 132 pins: 132 S
part 133 pins: 133 S
part 134 pins: 134 S
part 135 pins: 135 S
part 136 pins: 136 S
part 137 pins: 137 S
part 138 pins: 138 S
part 139 pins: 139 S
part 140 pins: 140 S
part 141 pins: 141 S
part 142 pins: 142 S
part 143 pins: 143 S
part 144 pins: 144 S
part 145 pins: 145 S
part 146 pins: 146 S
part 147 pins: 147 S
part 148 pins: 148 S
part 149 pins: 149 S
part 150 pins: 150 S
part 151 pins: 151 S
part 152 pins: 152 S
part 153 pins: 153 S
part 154 pins: 154 S
part 155 pins: 155 S
part 156 pins: 156 S
part 157 pins: 157 S
part 158 pins: 158 S
part 159 pins: 159 S
part 160 pins: 160 S

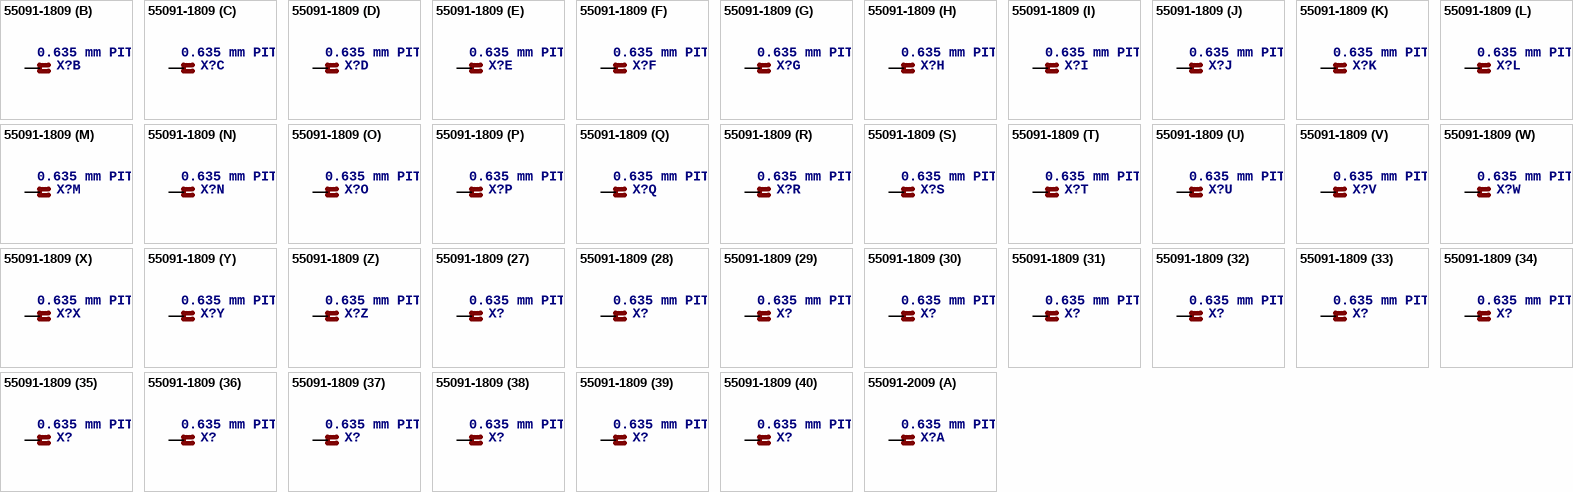
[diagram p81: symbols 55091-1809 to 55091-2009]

## 55091-1809
designator X?, comment 0.635 mm PITCH B TO B CONN.   Source: http://www.molex.com/pdm_docs/sd/550911609_sd.pdf
footprint 55091-1809
part A pins: 1 S
part B pins: 2 S
part C pins: 3 S
part D pins: 4 S
part E pins: 5 S
part F pins: 6 S
part G pins: 7 S
part H pins: 8 S
part I pins: 9 S
part J pins: 10 S
part K pins: 11 S
part L pins: 12 S
part M pins: 13 S
part N pins: 14 S
part O pins: 15 S
part P pins: 16 S
part Q pins: 17 S
part R pins: 18 S
part S pins: 19 S
part T pins: 20 S
part U pins: 21 S
part V pins: 22 S
part W pins: 23 S
part X pins: 24 S
part Y pins: 25 S
part Z pins: 26 S
part 27 pins: 27 S
part 28 pins: 28 S
part 29 pins: 29 S
part 30 pins: 30 S
part 31 pins: 31 S
part 32 pins: 32 S
part 33 pins: 33 S
part 34 pins: 34 S
part 35 pins: 35 S
part 36 pins: 36 S
part 37 pins: 37 S
part 38 pins: 38 S
part 39 pins: 39 S
part 40 pins: 40 S
part 41 pins: 41 S
part 42 pins: 42 S
part 43 pins: 43 S
part 44 pins: 44 S
part 45 pins: 45 S
part 46 pins: 46 S
part 47 pins: 47 S
part 48 pins: 48 S
part 49 pins: 49 S
part 50 pins: 50 S
part 51 pins: 51 S
part 52 pins: 52 S
part 53 pins: 53 S
part 54 pins: 54 S
part 55 pins: 55 S
part 56 pins: 56 S
part 57 pins: 57 S
part 58 pins: 58 S
part 59 pins: 59 S
part 60 pins: 60 S
part 61 pins: 61 S
part 62 pins: 62 S
part 63 pins: 63 S
part 64 pins: 64 S
part 65 pins: 65 S
part 66 pins: 66 S
part 67 pins: 67 S
part 68 pins: 68 S
part 69 pins: 69 S
part 70 pins: 70 S
part 71 pins: 71 S
part 72 pins: 72 S
part 73 pins: 73 S
part 74 pins: 74 S
part 75 pins: 75 S
part 76 pins: 76 S
part 77 pins: 77 S
part 78 pins: 78 S
part 79 pins: 79 S
part 80 pins: 80 S
part 81 pins: 81 S
part 82 pins: 82 S
part 83 pins: 83 S
part 84 pins: 84 S
part 85 pins: 85 S
part 86 pins: 86 S
part 87 pins: 87 S
part 88 pins: 88 S
part 89 pins: 89 S
part 90 pins: 90 S
part 91 pins: 91 S
part 92 pins: 92 S
part 93 pins: 93 S
part 94 pins: 94 S
part 95 pins: 95 S
part 96 pins: 96 S
part 97 pins: 97 S
part 98 pins: 98 S
part 99 pins: 99 S
part 100 pins: 100 S
part 101 pins: 101 S
part 102 pins: 102 S
part 103 pins: 103 S
part 104 pins: 104 S
part 105 pins: 105 S
part 106 pins: 106 S
part 107 pins: 107 S
part 108 pins: 108 S
part 109 pins: 109 S
part 110 pins: 110 S
part 111 pins: 111 S
part 112 pins: 112 S
part 113 pins: 113 S
part 114 pins: 114 S
part 115 pins: 115 S
part 116 pins: 116 S
part 117 pins: 117 S
part 118 pins: 118 S
part 119 pins: 119 S
part 120 pins: 120 S
part 121 pins: 121 S
part 122 pins: 122 S
part 123 pins: 123 S
part 124 pins: 124 S
part 125 pins: 125 S
part 126 pins: 126 S
part 127 pins: 127 S
part 128 pins: 128 S
part 129 pins: 129 S
part 130 pins: 130 S
part 131 pins: 131 S
part 132 pins: 132 S
part 133 pins: 133 S
part 134 pins: 134 S
part 135 pins: 135 S
part 136 pins: 136 S
part 137 pins: 137 S
part 138 pins: 138 S
part 139 pins: 139 S
part 140 pins: 140 S
part 141 pins: 141 S
part 142 pins: 142 S
part 143 pins: 143 S
part 144 pins: 144 S
part 145 pins: 145 S
part 146 pins: 146 S
part 147 pins: 147 S
part 148 pins: 148 S
part 149 pins: 149 S
part 150 pins: 150 S
part 151 pins: 151 S
part 152 pins: 152 S
part 153 pins: 153 S
part 154 pins: 154 S
part 155 pins: 155 S
part 156 pins: 156 S
part 157 pins: 157 S
part 158 pins: 158 S
part 159 pins: 159 S
part 160 pins: 160 S
part 161 pins: 161 S
part 162 pins: 162 S
part 163 pins: 163 S
part 164 pins: 164 S
part 165 pins: 165 S
part 166 pins: 166 S
part 167 pins: 167 S
part 168 pins: 168 S
part 169 pins: 169 S
part 170 pins: 170 S
part 171 pins: 171 S
part 172 pins: 172 S
part 173 pins: 173 S
part 174 pins: 174 S
part 175 pins: 175 S
part 176 pins: 176 S
part 177 pins: 177 S
part 178 pins: 178 S
part 179 pins: 179 S
part 180 pins: 180 S

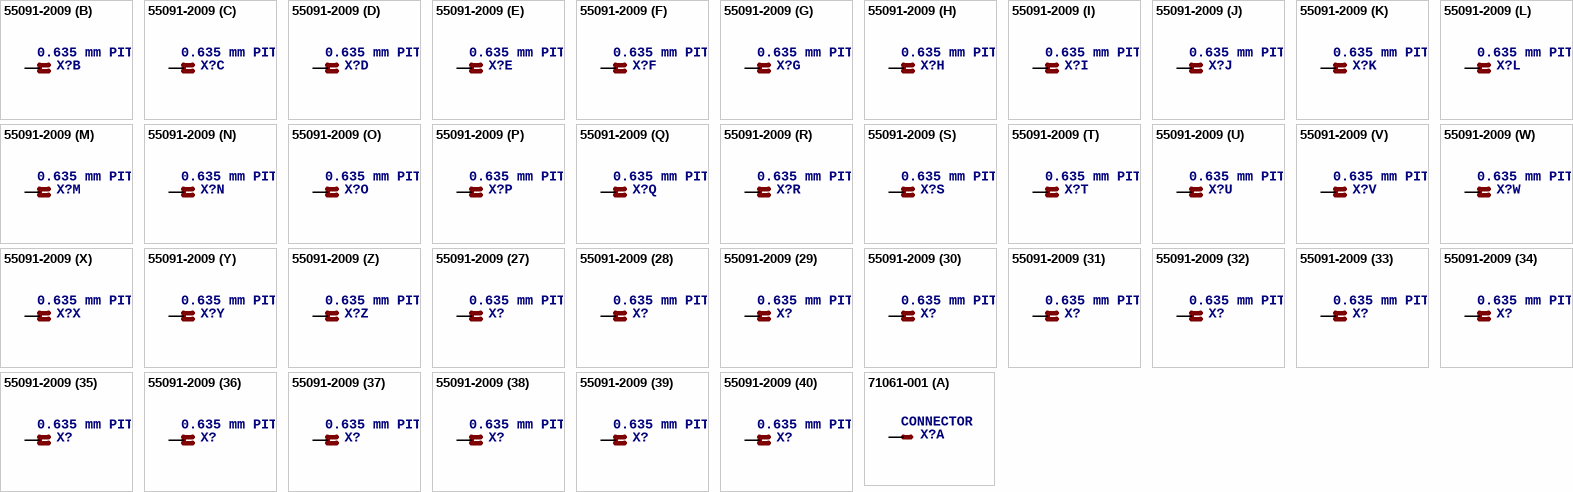
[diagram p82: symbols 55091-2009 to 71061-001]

## 55091-2009
designator X?, comment 0.635 mm PITCH B TO B CONN.   Source: http://www.molex.com/pdm_docs/sd/550911609_sd.pdf
footprint 55091-2009
part A pins: 1 S
part B pins: 2 S
part C pins: 3 S
part D pins: 4 S
part E pins: 5 S
part F pins: 6 S
part G pins: 7 S
part H pins: 8 S
part I pins: 9 S
part J pins: 10 S
part K pins: 11 S
part L pins: 12 S
part M pins: 13 S
part N pins: 14 S
part O pins: 15 S
part P pins: 16 S
part Q pins: 17 S
part R pins: 18 S
part S pins: 19 S
part T pins: 20 S
part U pins: 21 S
part V pins: 22 S
part W pins: 23 S
part X pins: 24 S
part Y pins: 25 S
part Z pins: 26 S
part 27 pins: 27 S
part 28 pins: 28 S
part 29 pins: 29 S
part 30 pins: 30 S
part 31 pins: 31 S
part 32 pins: 32 S
part 33 pins: 33 S
part 34 pins: 34 S
part 35 pins: 35 S
part 36 pins: 36 S
part 37 pins: 37 S
part 38 pins: 38 S
part 39 pins: 39 S
part 40 pins: 40 S
part 41 pins: 41 S
part 42 pins: 42 S
part 43 pins: 43 S
part 44 pins: 44 S
part 45 pins: 45 S
part 46 pins: 46 S
part 47 pins: 47 S
part 48 pins: 48 S
part 49 pins: 49 S
part 50 pins: 50 S
part 51 pins: 51 S
part 52 pins: 52 S
part 53 pins: 53 S
part 54 pins: 54 S
part 55 pins: 55 S
part 56 pins: 56 S
part 57 pins: 57 S
part 58 pins: 58 S
part 59 pins: 59 S
part 60 pins: 60 S
part 61 pins: 61 S
part 62 pins: 62 S
part 63 pins: 63 S
part 64 pins: 64 S
part 65 pins: 65 S
part 66 pins: 66 S
part 67 pins: 67 S
part 68 pins: 68 S
part 69 pins: 69 S
part 70 pins: 70 S
part 71 pins: 71 S
part 72 pins: 72 S
part 73 pins: 73 S
part 74 pins: 74 S
part 75 pins: 75 S
part 76 pins: 76 S
part 77 pins: 77 S
part 78 pins: 78 S
part 79 pins: 79 S
part 80 pins: 80 S
part 81 pins: 81 S
part 82 pins: 82 S
part 83 pins: 83 S
part 84 pins: 84 S
part 85 pins: 85 S
part 86 pins: 86 S
part 87 pins: 87 S
part 88 pins: 88 S
part 89 pins: 89 S
part 90 pins: 90 S
part 91 pins: 91 S
part 92 pins: 92 S
part 93 pins: 93 S
part 94 pins: 94 S
part 95 pins: 95 S
part 96 pins: 96 S
part 97 pins: 97 S
part 98 pins: 98 S
part 99 pins: 99 S
part 100 pins: 100 S
part 101 pins: 101 S
part 102 pins: 102 S
part 103 pins: 103 S
part 104 pins: 104 S
part 105 pins: 105 S
part 106 pins: 106 S
part 107 pins: 107 S
part 108 pins: 108 S
part 109 pins: 109 S
part 110 pins: 110 S
part 111 pins: 111 S
part 112 pins: 112 S
part 113 pins: 113 S
part 114 pins: 114 S
part 115 pins: 115 S
part 116 pins: 116 S
part 117 pins: 117 S
part 118 pins: 118 S
part 119 pins: 119 S
part 120 pins: 120 S
part 121 pins: 121 S
part 122 pins: 122 S
part 123 pins: 123 S
part 124 pins: 124 S
part 125 pins: 125 S
part 126 pins: 126 S
part 127 pins: 127 S
part 128 pins: 128 S
part 129 pins: 129 S
part 130 pins: 130 S
part 131 pins: 131 S
part 132 pins: 132 S
part 133 pins: 133 S
part 134 pins: 134 S
part 135 pins: 135 S
part 136 pins: 136 S
part 137 pins: 137 S
part 138 pins: 138 S
part 139 pins: 139 S
part 140 pins: 140 S
part 141 pins: 141 S
part 142 pins: 142 S
part 143 pins: 143 S
part 144 pins: 144 S
part 145 pins: 145 S
part 146 pins: 146 S
part 147 pins: 147 S
part 148 pins: 148 S
part 149 pins: 149 S
part 150 pins: 150 S
part 151 pins: 151 S
part 152 pins: 152 S
part 153 pins: 153 S
part 154 pins: 154 S
part 155 pins: 155 S
part 156 pins: 156 S
part 157 pins: 157 S
part 158 pins: 158 S
part 159 pins: 159 S
part 160 pins: 160 S
part 161 pins: 161 S
part 162 pins: 162 S
part 163 pins: 163 S
part 164 pins: 164 S
part 165 pins: 165 S
part 166 pins: 166 S
part 167 pins: 167 S
part 168 pins: 168 S
part 169 pins: 169 S
part 170 pins: 170 S
part 171 pins: 171 S
part 172 pins: 172 S
part 173 pins: 173 S
part 174 pins: 174 S
part 175 pins: 175 S
part 176 pins: 176 S
part 177 pins: 177 S
part 178 pins: 178 S
part 179 pins: 179 S
part 180 pins: 180 S
part 181 pins: 181 S
part 182 pins: 182 S
part 183 pins: 183 S
part 184 pins: 184 S
part 185 pins: 185 S
part 186 pins: 186 S
part 187 pins: 187 S
part 188 pins: 188 S
part 189 pins: 189 S
part 190 pins: 190 S
part 191 pins: 191 S
part 192 pins: 192 S
part 193 pins: 193 S
part 194 pins: 194 S
part 195 pins: 195 S
part 196 pins: 196 S
part 197 pins: 197 S
part 198 pins: 198 S
part 199 pins: 199 S
part 200 pins: 200 S

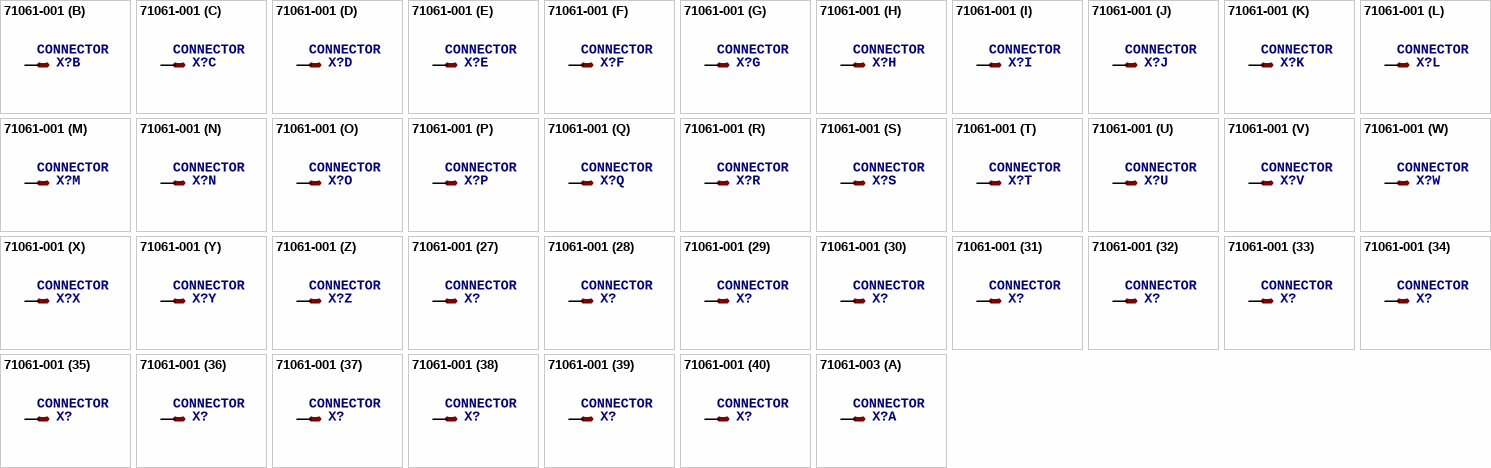
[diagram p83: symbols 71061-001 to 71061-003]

## 71061-001
designator X?, comment CONNECTOR   50-pin 1.27mm (.050 inch) pitch SCSI+ unshielded receptacle   right angle   all plastic
footprint 71061-0001
part A pins: 1 S
part B pins: 2 S
part C pins: 3 S
part D pins: 4 S
part E pins: 5 S
part F pins: 6 S
part G pins: 7 S
part H pins: 8 S
part I pins: 9 S
part J pins: 10 S
part K pins: 11 S
part L pins: 12 S
part M pins: 13 S
part N pins: 14 S
part O pins: 15 S
part P pins: 16 S
part Q pins: 17 S
part R pins: 18 S
part S pins: 19 S
part T pins: 20 S
part U pins: 21 S
part V pins: 22 S
part W pins: 23 S
part X pins: 24 S
part Y pins: 25 S
part Z pins: 26 S
part 27 pins: 27 S
part 28 pins: 28 S
part 29 pins: 29 S
part 30 pins: 30 S
part 31 pins: 31 S
part 32 pins: 32 S
part 33 pins: 33 S
part 34 pins: 34 S
part 35 pins: 35 S
part 36 pins: 36 S
part 37 pins: 37 S
part 38 pins: 38 S
part 39 pins: 39 S
part 40 pins: 40 S
part 41 pins: 41 S
part 42 pins: 42 S
part 43 pins: 43 S
part 44 pins: 44 S
part 45 pins: 45 S
part 46 pins: 46 S
part 47 pins: 47 S
part 48 pins: 48 S
part 49 pins: 49 S
part 50 pins: 50 S

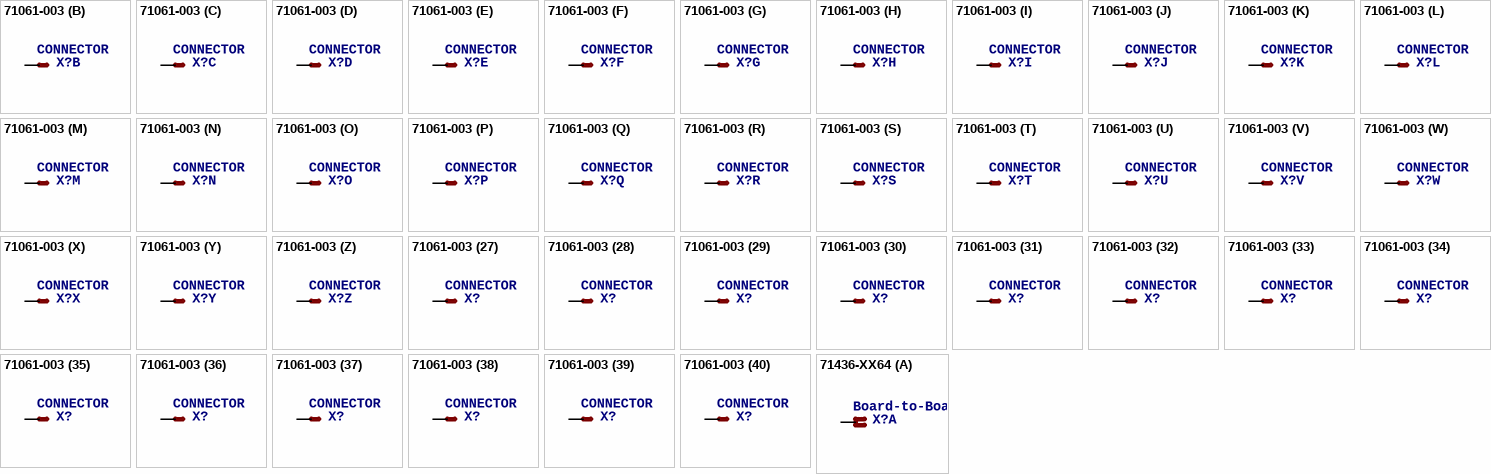
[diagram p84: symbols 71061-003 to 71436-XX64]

## 71061-003
designator X?, comment CONNECTOR   68-pin 1.27mm (.050 inch) pitch SCSI+ unshielded receptacle   right angle   all plastic
footprint 71061-0003
part A pins: 1 S
part B pins: 2 S
part C pins: 3 S
part D pins: 4 S
part E pins: 5 S
part F pins: 6 S
part G pins: 7 S
part H pins: 8 S
part I pins: 9 S
part J pins: 10 S
part K pins: 11 S
part L pins: 12 S
part M pins: 13 S
part N pins: 14 S
part O pins: 15 S
part P pins: 16 S
part Q pins: 17 S
part R pins: 18 S
part S pins: 19 S
part T pins: 20 S
part U pins: 21 S
part V pins: 22 S
part W pins: 23 S
part X pins: 24 S
part Y pins: 25 S
part Z pins: 26 S
part 27 pins: 27 S
part 28 pins: 28 S
part 29 pins: 29 S
part 30 pins: 30 S
part 31 pins: 31 S
part 32 pins: 32 S
part 33 pins: 33 S
part 34 pins: 34 S
part 35 pins: 35 S
part 36 pins: 36 S
part 37 pins: 37 S
part 38 pins: 38 S
part 39 pins: 39 S
part 40 pins: 40 S
part 41 pins: 41 S
part 42 pins: 42 S
part 43 pins: 43 S
part 44 pins: 44 S
part 45 pins: 45 S
part 46 pins: 46 S
part 47 pins: 47 S
part 48 pins: 48 S
part 49 pins: 49 S
part 50 pins: 50 S
part 51 pins: 51 S
part 52 pins: 52 S
part 53 pins: 53 S
part 54 pins: 54 S
part 55 pins: 55 S
part 56 pins: 56 S
part 57 pins: 57 S
part 58 pins: 58 S
part 59 pins: 59 S
part 60 pins: 60 S
part 61 pins: 61 S
part 62 pins: 62 S
part 63 pins: 63 S
part 64 pins: 64 S
part 65 pins: 65 S
part 66 pins: 66 S
part 67 pins: 67 S
part 68 pins: 68 S

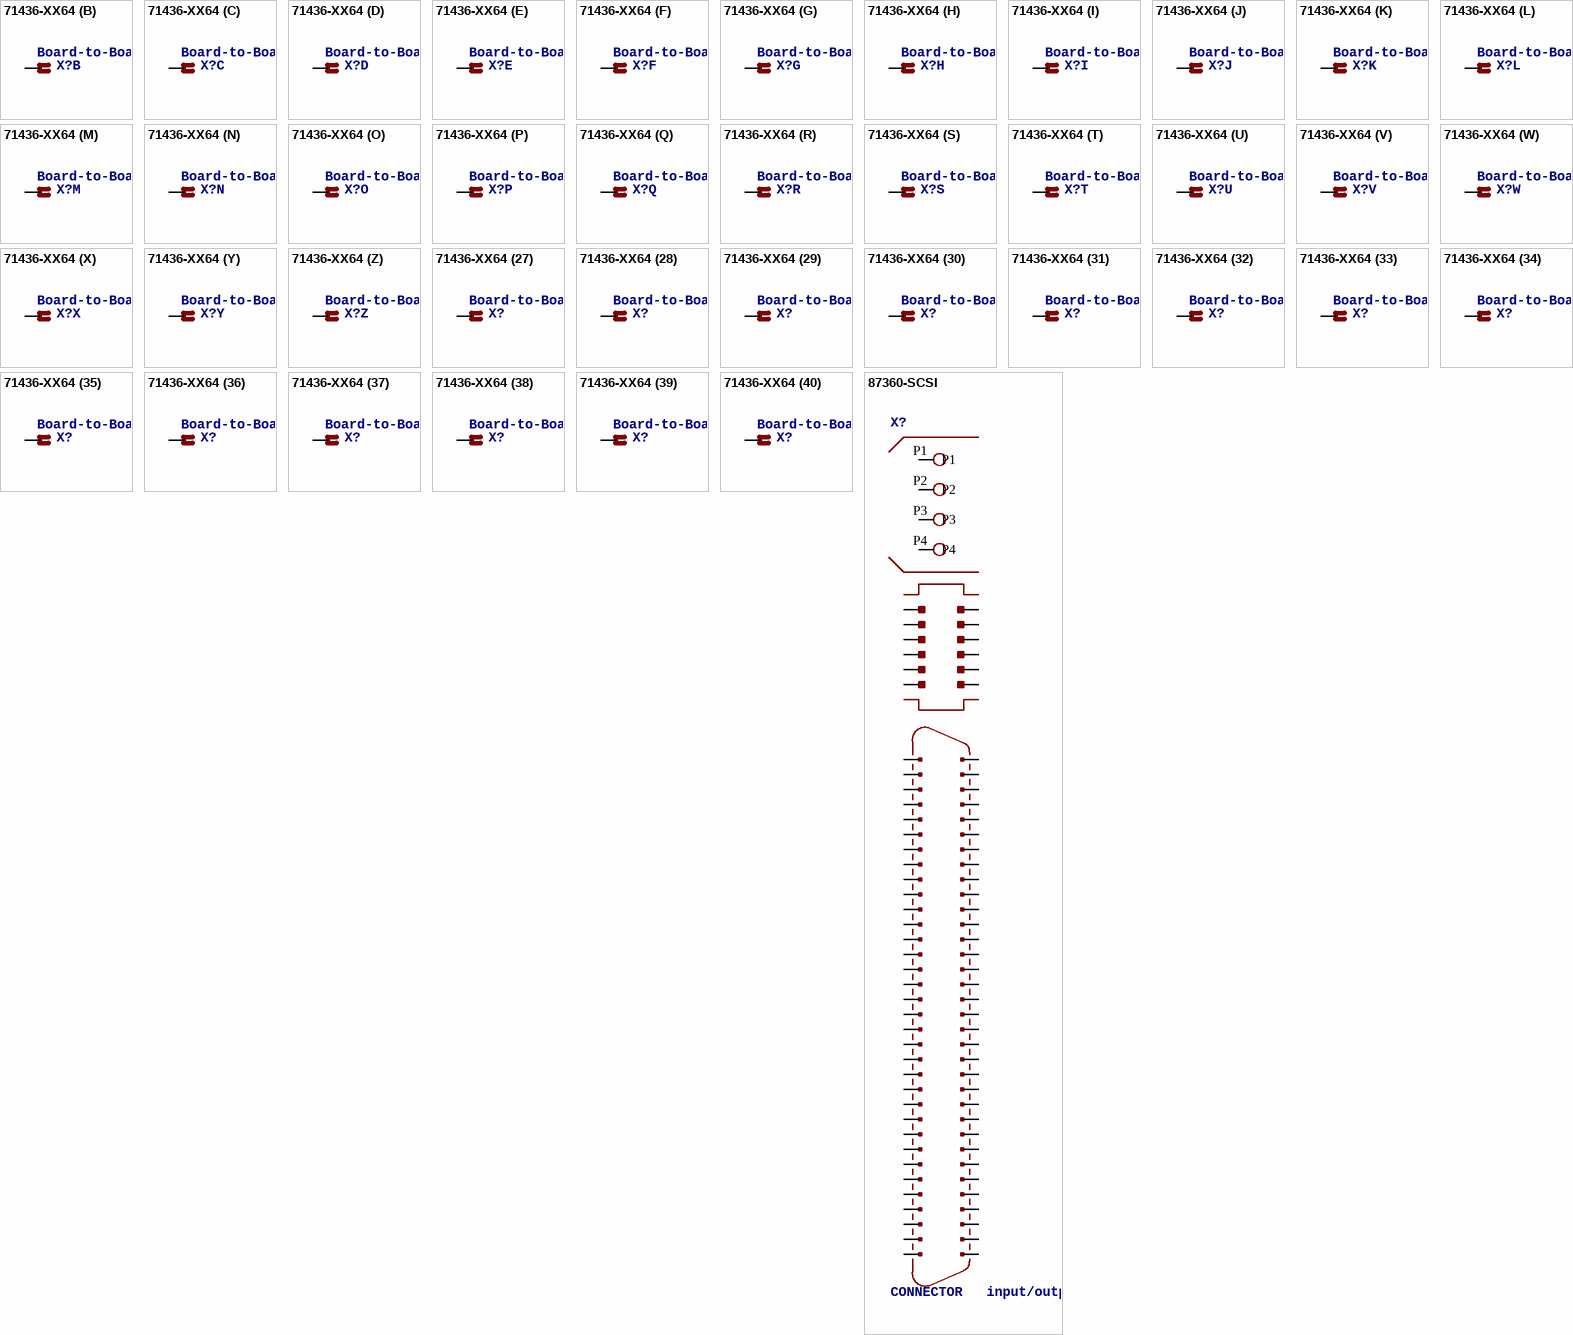
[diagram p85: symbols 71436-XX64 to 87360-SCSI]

## 71436-XX64
designator X?, comment Board-to-Board Connector 1.00mm (.039") Mezzanine IEEE 1386 Plug - Dual Row, SMT, Vertical Stacking   Source: http://www.molex.com/product/micro/71436.html
footprint 71436-XX64
part A pins: 1 S
part B pins: 2 S
part C pins: 3 S
part D pins: 4 S
part E pins: 5 S
part F pins: 6 S
part G pins: 7 S
part H pins: 8 S
part I pins: 9 S
part J pins: 10 S
part K pins: 11 S
part L pins: 12 S
part M pins: 13 S
part N pins: 14 S
part O pins: 15 S
part P pins: 16 S
part Q pins: 17 S
part R pins: 18 S
part S pins: 19 S
part T pins: 20 S
part U pins: 21 S
part V pins: 22 S
part W pins: 23 S
part X pins: 24 S
part Y pins: 25 S
part Z pins: 26 S
part 27 pins: 27 S
part 28 pins: 28 S
part 29 pins: 29 S
part 30 pins: 30 S
part 31 pins: 31 S
part 32 pins: 32 S
part 33 pins: 33 S
part 34 pins: 34 S
part 35 pins: 35 S
part 36 pins: 36 S
part 37 pins: 37 S
part 38 pins: 38 S
part 39 pins: 39 S
part 40 pins: 40 S
part 41 pins: 41 S
part 42 pins: 42 S
part 43 pins: 43 S
part 44 pins: 44 S
part 45 pins: 45 S
part 46 pins: 46 S
part 47 pins: 47 S
part 48 pins: 48 S
part 49 pins: 49 S
part 50 pins: 50 S
part 51 pins: 51 S
part 52 pins: 52 S
part 53 pins: 53 S
part 54 pins: 54 S
part 55 pins: 55 S
part 56 pins: 56 S
part 57 pins: 57 S
part 58 pins: 58 S
part 59 pins: 59 S
part 60 pins: 60 S
part 61 pins: 61 S
part 62 pins: 62 S
part 63 pins: 63 S
part 64 pins: 64 S

## 87360-SCSI
designator X?, comment CONNECTOR   input/output 3 in 1 combo connector   wide SCSI, 2.00 mm, power, right angle
footprint 87360-SCSI
pins: 1, 2, 3, 4, 5, 6, 7, 8, 9, 10, 11, 12, 13, 14, 15, 16, 17, 18, 19, 20, 21, 22, 23, 24, 25, 26, 27, 28, 29, 30, 31, 32, 33, 34, 35, 36, 37, 38, 39, 40, 41, 42, 43, 44, 45, 46, 47, 48, 49, 50, 51, 52, 53, 54, 55, 56, 57, 58, 59, 60, 61, 62, 63, 64, 65, 66, 67, 68, J1, J2, J3, J4, J5, J6, J7, J8, J9, J10, J11, J12, P1, P2, P3, P4

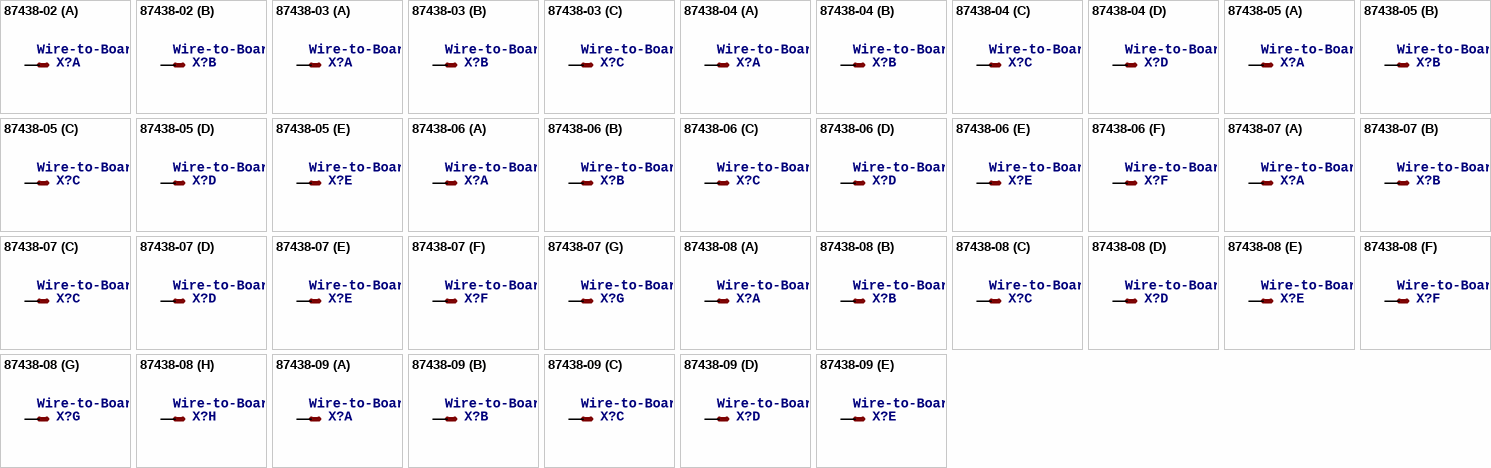
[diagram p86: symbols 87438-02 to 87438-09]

## 87438-02
designator X?, comment Wire-to-Board  1.50mm (.059") Pitch Header - Right Angle, SMT, Shrouded   Source: http://www.molex.com/product/micro/87438.html
footprint 87438-02
part A pins: 1 S
part B pins: 2 S

## 87438-03
designator X?, comment Wire-to-Board  1.50mm (.059") Pitch Header - Right Angle, SMT, Shrouded   Source: http://www.molex.com/product/micro/87438.html
footprint 87438-03
part A pins: 1 S
part B pins: 2 S
part C pins: 3 S

## 87438-04
designator X?, comment Wire-to-Board  1.50mm (.059") Pitch Header - Right Angle, SMT, Shrouded   Source: http://www.molex.com/product/micro/87438.html
footprint 87438-04
part A pins: 1 S
part B pins: 2 S
part C pins: 3 S
part D pins: 4 S

## 87438-05
designator X?, comment Wire-to-Board  1.50mm (.059") Pitch Header - Right Angle, SMT, Shrouded   Source: http://www.molex.com/product/micro/87438.html
MPN: 87438-0542
footprint 87438-05
part A pins: 1 S
part B pins: 2 S
part C pins: 3 S
part D pins: 4 S
part E pins: 5 S

## 87438-06
designator X?, comment Wire-to-Board  1.50mm (.059") Pitch Header - Right Angle, SMT, Shrouded   Source: http://www.molex.com/product/micro/87438.html
MPN: 87438-0643
footprint 87438-06
part A pins: 1 S
part B pins: 2 S
part C pins: 3 S
part D pins: 4 S
part E pins: 5 S
part F pins: 6 S

## 87438-07
designator X?, comment Wire-to-Board  1.50mm (.059") Pitch Header - Right Angle, SMT, Shrouded   Source: http://www.molex.com/product/micro/87438.html
MPN: 87438-0733; MF: WALDOM/MOLEX
footprint 87438-07
part A pins: 1 S
part B pins: 2 S
part C pins: 3 S
part D pins: 4 S
part E pins: 5 S
part F pins: 6 S
part G pins: 7 S

## 87438-08
designator X?, comment Wire-to-Board  1.50mm (.059") Pitch Header - Right Angle, SMT, Shrouded   Source: http://www.molex.com/product/micro/87438.html
footprint 87438-08
part A pins: 1 S
part B pins: 2 S
part C pins: 3 S
part D pins: 4 S
part E pins: 5 S
part F pins: 6 S
part G pins: 7 S
part H pins: 8 S

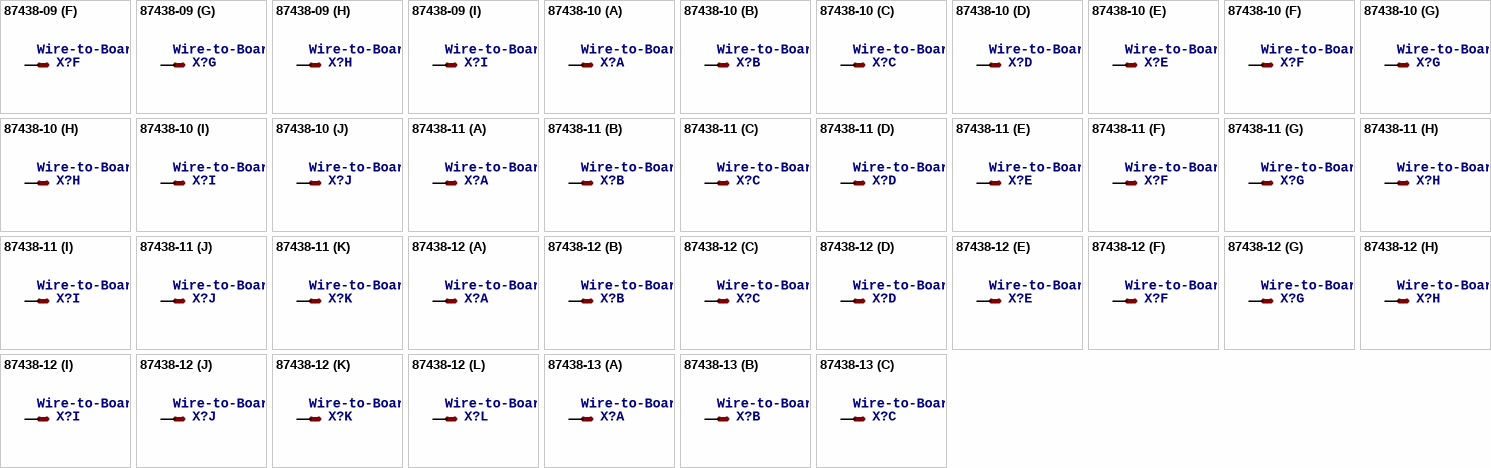
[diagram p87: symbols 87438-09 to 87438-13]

## 87438-09
designator X?, comment Wire-to-Board  1.50mm (.059") Pitch Header - Right Angle, SMT, Shrouded   Source: http://www.molex.com/product/micro/87438.html
footprint 87438-09
part A pins: 1 S
part B pins: 2 S
part C pins: 3 S
part D pins: 4 S
part E pins: 5 S
part F pins: 6 S
part G pins: 7 S
part H pins: 8 S
part I pins: 9 S

## 87438-10
designator X?, comment Wire-to-Board  1.50mm (.059") Pitch Header - Right Angle, SMT, Shrouded   Source: http://www.molex.com/product/micro/87438.html
footprint 87438-10
part A pins: 1 S
part B pins: 2 S
part C pins: 3 S
part D pins: 4 S
part E pins: 5 S
part F pins: 6 S
part G pins: 7 S
part H pins: 8 S
part I pins: 9 S
part J pins: 10 S

## 87438-11
designator X?, comment Wire-to-Board  1.50mm (.059") Pitch Header - Right Angle, SMT, Shrouded   Source: http://www.molex.com/product/micro/87438.html
MPN: 87438-1142
footprint 87438-11
part A pins: 1 S
part B pins: 2 S
part C pins: 3 S
part D pins: 4 S
part E pins: 5 S
part F pins: 6 S
part G pins: 7 S
part H pins: 8 S
part I pins: 9 S
part J pins: 10 S
part K pins: 11 S

## 87438-12
designator X?, comment Wire-to-Board  1.50mm (.059") Pitch Header - Right Angle, SMT, Shrouded   Source: http://www.molex.com/product/micro/87438.html
footprint 87438-12
part A pins: 1 S
part B pins: 2 S
part C pins: 3 S
part D pins: 4 S
part E pins: 5 S
part F pins: 6 S
part G pins: 7 S
part H pins: 8 S
part I pins: 9 S
part J pins: 10 S
part K pins: 11 S
part L pins: 12 S

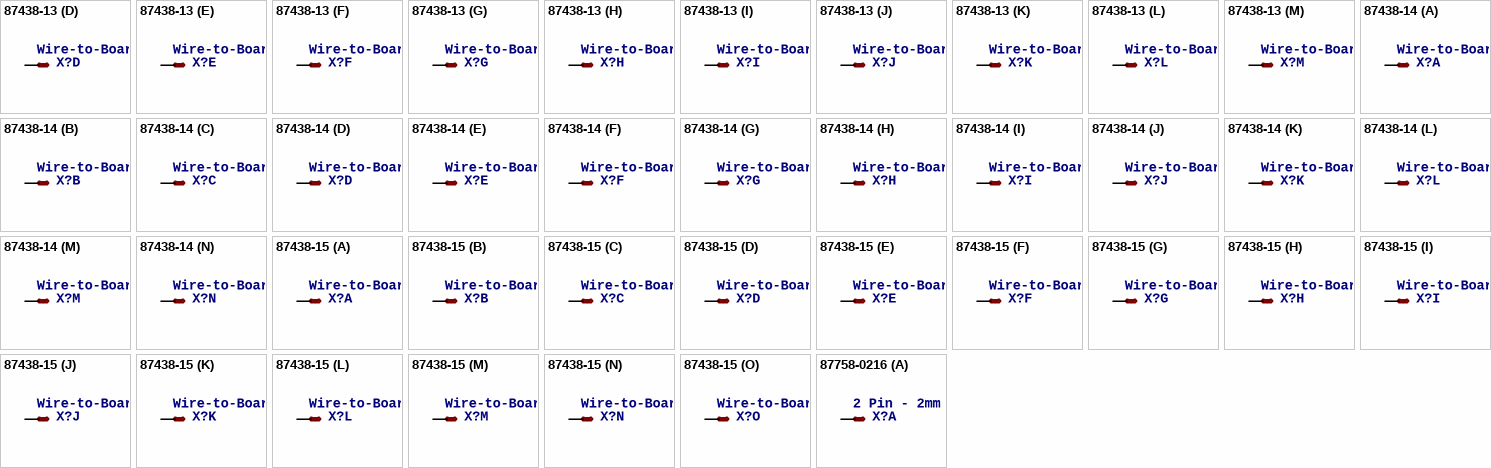
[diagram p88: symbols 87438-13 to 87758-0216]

## 87438-13
designator X?, comment Wire-to-Board  1.50mm (.059") Pitch Header - Right Angle, SMT, Shrouded   Source: http://www.molex.com/product/micro/87438.html
MPN: 87438-1343
footprint 87438-13
part A pins: 1 S
part B pins: 2 S
part C pins: 3 S
part D pins: 4 S
part E pins: 5 S
part F pins: 6 S
part G pins: 7 S
part H pins: 8 S
part I pins: 9 S
part J pins: 10 S
part K pins: 11 S
part L pins: 12 S
part M pins: 13 S

## 87438-14
designator X?, comment Wire-to-Board  1.50mm (.059") Pitch Header - Right Angle, SMT, Shrouded   Source: http://www.molex.com/product/micro/87438.html
MPN: 87438-1443
footprint 87438-14
part A pins: 1 S
part B pins: 2 S
part C pins: 3 S
part D pins: 4 S
part E pins: 5 S
part F pins: 6 S
part G pins: 7 S
part H pins: 8 S
part I pins: 9 S
part J pins: 10 S
part K pins: 11 S
part L pins: 12 S
part M pins: 13 S
part N pins: 14 S

## 87438-15
designator X?, comment Wire-to-Board  1.50mm (.059") Pitch Header - Right Angle, SMT, Shrouded   Source: http://www.molex.com/product/micro/87438.html
MPN: 87438-1542
footprint 87438-15
part A pins: 1 S
part B pins: 2 S
part C pins: 3 S
part D pins: 4 S
part E pins: 5 S
part F pins: 6 S
part G pins: 7 S
part H pins: 8 S
part I pins: 9 S
part J pins: 10 S
part K pins: 11 S
part L pins: 12 S
part M pins: 13 S
part N pins: 14 S
part O pins: 15 S

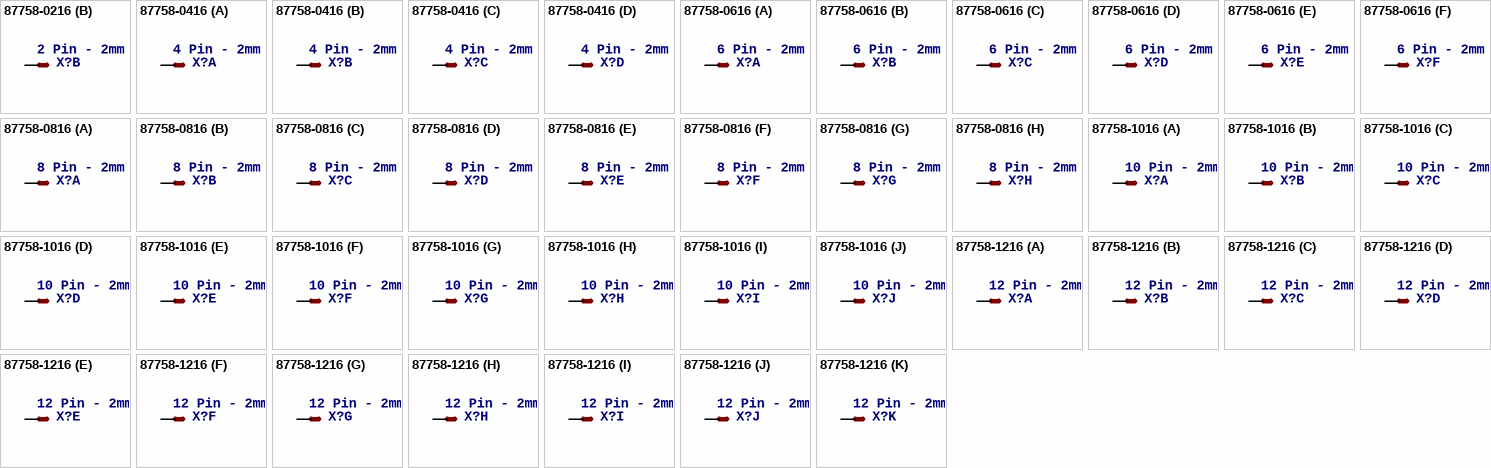
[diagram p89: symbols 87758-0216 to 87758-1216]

## 87758-0216
designator X?, comment 2 Pin - 2mm Dual Row Single Wafer, Vertical T/H HDR   Source: http://www.molex.com/pdm_docs/sd/877580616_sd.pdf
MPN: 87758-0216
footprint 87758-0216
part A pins: 1 S
part B pins: 2 S

## 87758-0416
designator X?, comment 4 Pin - 2mm Dual Row Single Wafer, Vertical T/H HDR   Source: http://www.molex.com/pdm_docs/sd/877580616_sd.pdf
MPN: 87758-0416; MF: FARNELL
footprint 87758-0416
part A pins: 1 S
part B pins: 2 S
part C pins: 3 S
part D pins: 4 S

## 87758-0616
designator X?, comment 6 Pin - 2mm Dual Row Single Wafer, Vertical T/H HDR   Source: http://www.molex.com/pdm_docs/sd/877580616_sd.pdf
MPN: 87758-0616
footprint 87758-0616
part A pins: 1 S
part B pins: 2 S
part C pins: 3 S
part D pins: 4 S
part E pins: 5 S
part F pins: 6 S

## 87758-0816
designator X?, comment 8 Pin - 2mm Dual Row Single Wafer, Vertical T/H HDR   Source: http://www.molex.com/pdm_docs/sd/877580616_sd.pdf
MPN: 87758-0816; MF: MOLEX
footprint 87758-0816
part A pins: 1 S
part B pins: 2 S
part C pins: 3 S
part D pins: 4 S
part E pins: 5 S
part F pins: 6 S
part G pins: 7 S
part H pins: 8 S

## 87758-1016
designator X?, comment 10 Pin - 2mm Dual Row Single Wafer, Vertical T/H HDR   Source: http://www.molex.com/pdm_docs/sd/877580616_sd.pdf
MPN: 87758-1016; MF: MOLEX
footprint 87758-1016
part A pins: 1 S
part B pins: 2 S
part C pins: 3 S
part D pins: 4 S
part E pins: 5 S
part F pins: 6 S
part G pins: 7 S
part H pins: 8 S
part I pins: 9 S
part J pins: 10 S

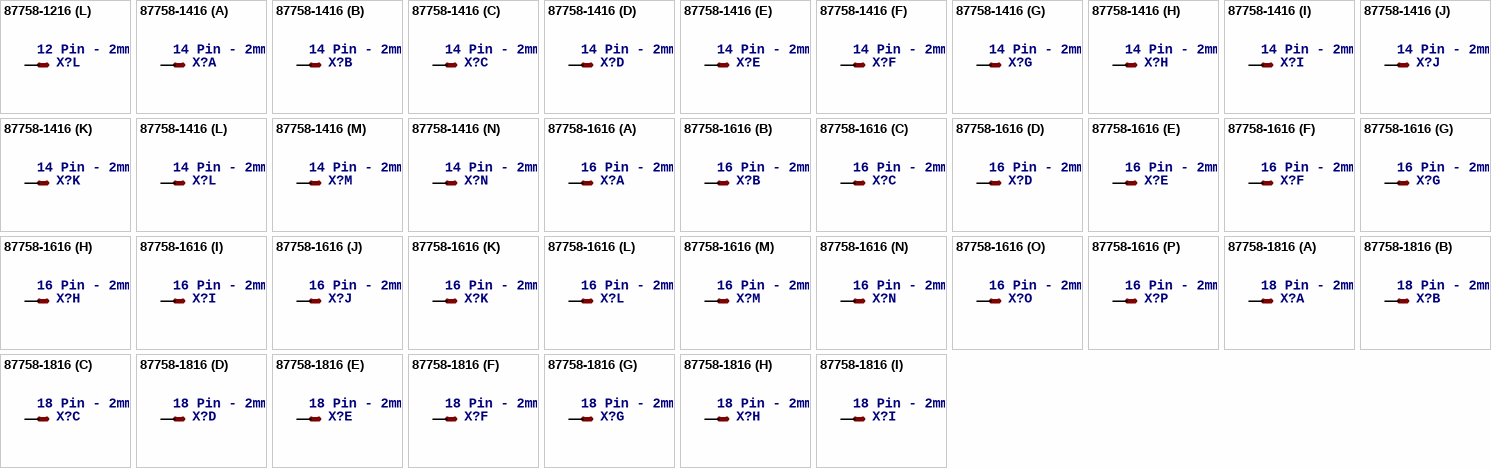
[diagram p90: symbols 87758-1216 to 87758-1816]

## 87758-1216
designator X?, comment 12 Pin - 2mm Dual Row Single Wafer, Vertical T/H HDR   Source: http://www.molex.com/pdm_docs/sd/877580616_sd.pdf
MPN: 87758-1216
footprint 87758-1216
part A pins: 1 S
part B pins: 2 S
part C pins: 3 S
part D pins: 4 S
part E pins: 5 S
part F pins: 6 S
part G pins: 7 S
part H pins: 8 S
part I pins: 9 S
part J pins: 10 S
part K pins: 11 S
part L pins: 12 S

## 87758-1416
designator X?, comment 14 Pin - 2mm Dual Row Single Wafer, Vertical T/H HDR   Source: http://www.molex.com/pdm_docs/sd/877580616_sd.pdf
MPN: 87758-1416; MF: MOLEX
footprint 87758-1416
part A pins: 1 S
part B pins: 2 S
part C pins: 3 S
part D pins: 4 S
part E pins: 5 S
part F pins: 6 S
part G pins: 7 S
part H pins: 8 S
part I pins: 9 S
part J pins: 10 S
part K pins: 11 S
part L pins: 12 S
part M pins: 13 S
part N pins: 14 S

## 87758-1616
designator X?, comment 16 Pin - 2mm Dual Row Single Wafer, Vertical T/H HDR   Source: http://www.molex.com/pdm_docs/sd/877580616_sd.pdf
MPN: 87758-1616; MF: MOLEX
footprint 87758-1616
part A pins: 1 S
part B pins: 2 S
part C pins: 3 S
part D pins: 4 S
part E pins: 5 S
part F pins: 6 S
part G pins: 7 S
part H pins: 8 S
part I pins: 9 S
part J pins: 10 S
part K pins: 11 S
part L pins: 12 S
part M pins: 13 S
part N pins: 14 S
part O pins: 15 S
part P pins: 16 S

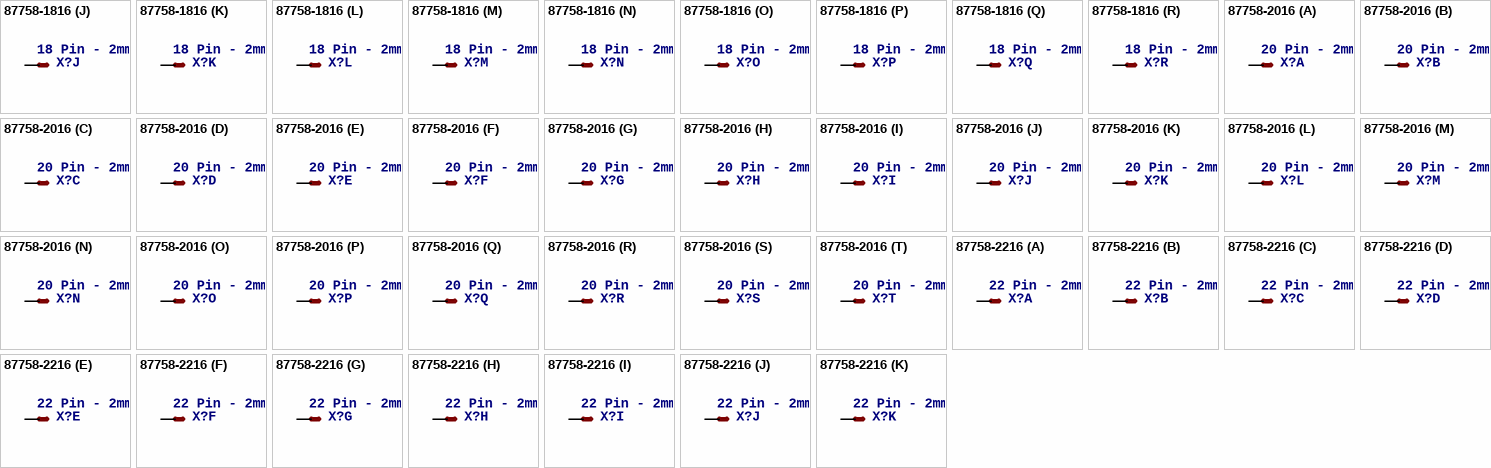
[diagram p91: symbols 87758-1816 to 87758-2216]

## 87758-1816
designator X?, comment 18 Pin - 2mm Dual Row Single Wafer, Vertical T/H HDR   Source: http://www.molex.com/pdm_docs/sd/877580616_sd.pdf
MPN: 87758-1816
footprint 87758-1816
part A pins: 1 S
part B pins: 2 S
part C pins: 3 S
part D pins: 4 S
part E pins: 5 S
part F pins: 6 S
part G pins: 7 S
part H pins: 8 S
part I pins: 9 S
part J pins: 10 S
part K pins: 11 S
part L pins: 12 S
part M pins: 13 S
part N pins: 14 S
part O pins: 15 S
part P pins: 16 S
part Q pins: 17 S
part R pins: 18 S

## 87758-2016
designator X?, comment 20 Pin - 2mm Dual Row Single Wafer, Vertical T/H HDR   Source: http://www.molex.com/pdm_docs/sd/877580616_sd.pdf
MPN: 87758-2016
footprint 87758-2016
part A pins: 1 S
part B pins: 2 S
part C pins: 3 S
part D pins: 4 S
part E pins: 5 S
part F pins: 6 S
part G pins: 7 S
part H pins: 8 S
part I pins: 9 S
part J pins: 10 S
part K pins: 11 S
part L pins: 12 S
part M pins: 13 S
part N pins: 14 S
part O pins: 15 S
part P pins: 16 S
part Q pins: 17 S
part R pins: 18 S
part S pins: 19 S
part T pins: 20 S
